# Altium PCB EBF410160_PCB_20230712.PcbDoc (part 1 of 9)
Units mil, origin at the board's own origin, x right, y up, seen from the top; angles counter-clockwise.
Board outline 5393.69 x 3858.26 mil, 6 copper layers (TOP, GND02, ART03, POW04, GND05, BOTTOM), stack 47.2 mil thick; 572 components, 434 nets, 2057 pads, 1177 vias.
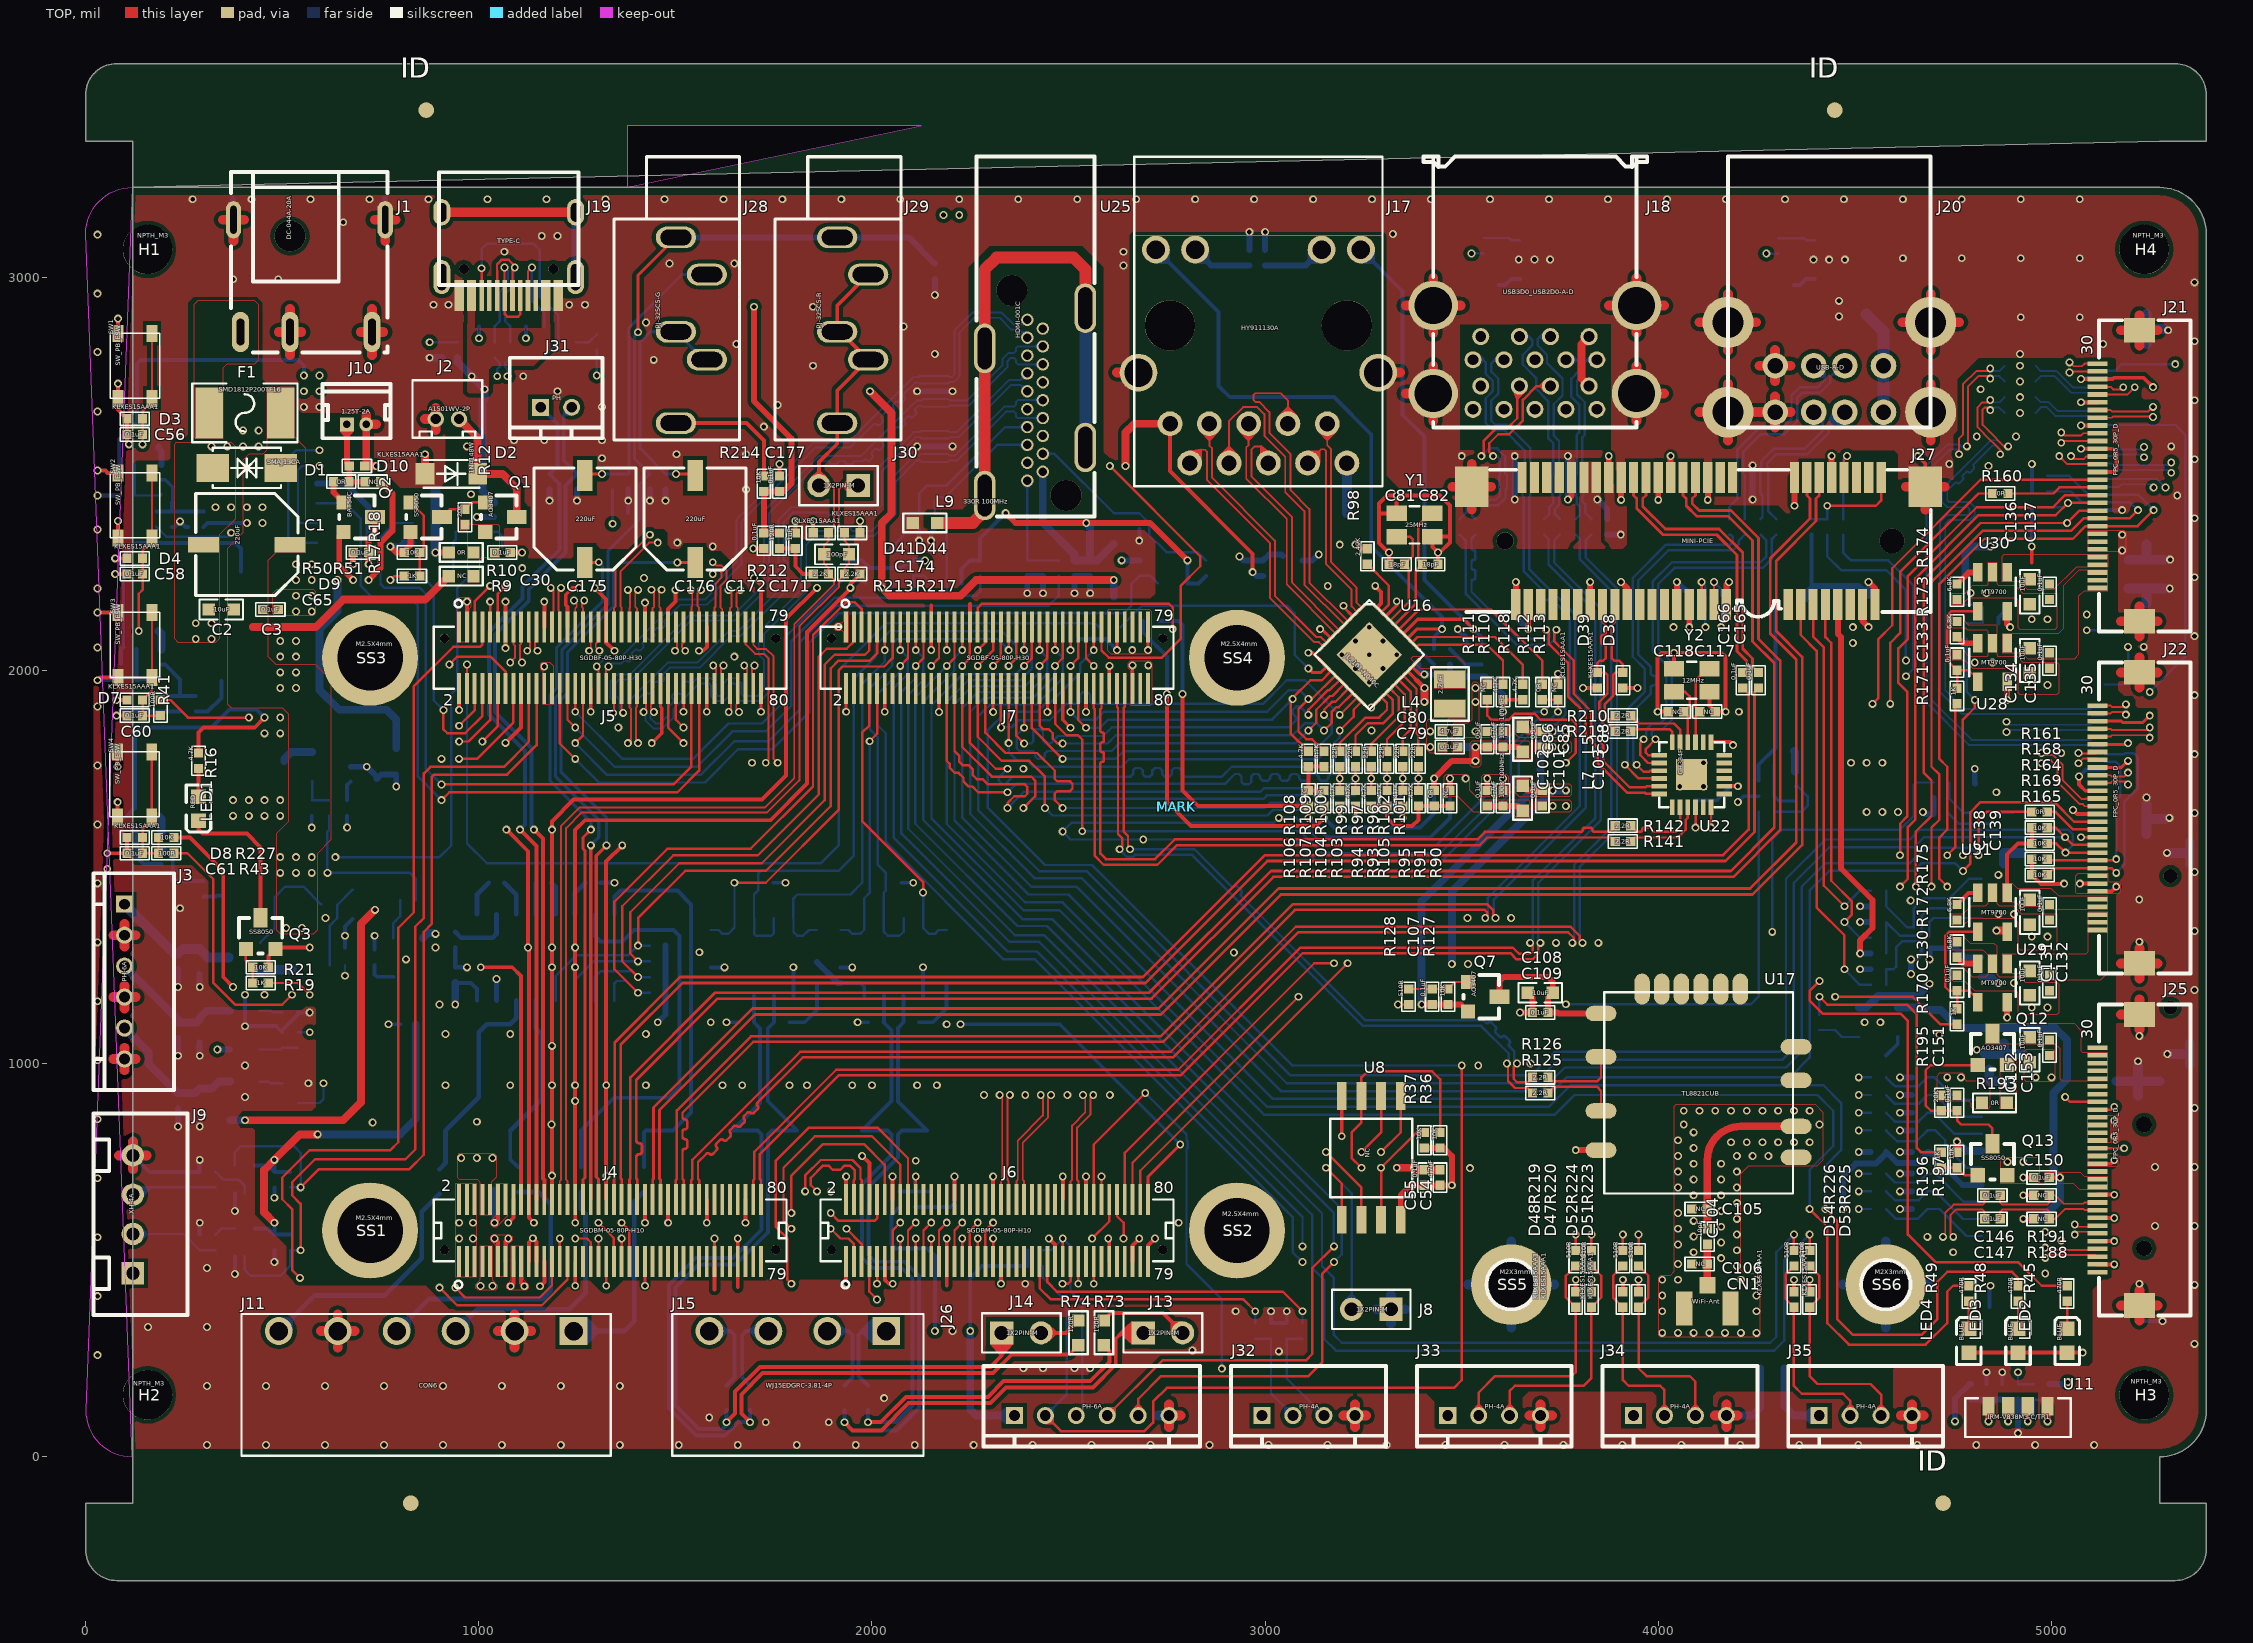
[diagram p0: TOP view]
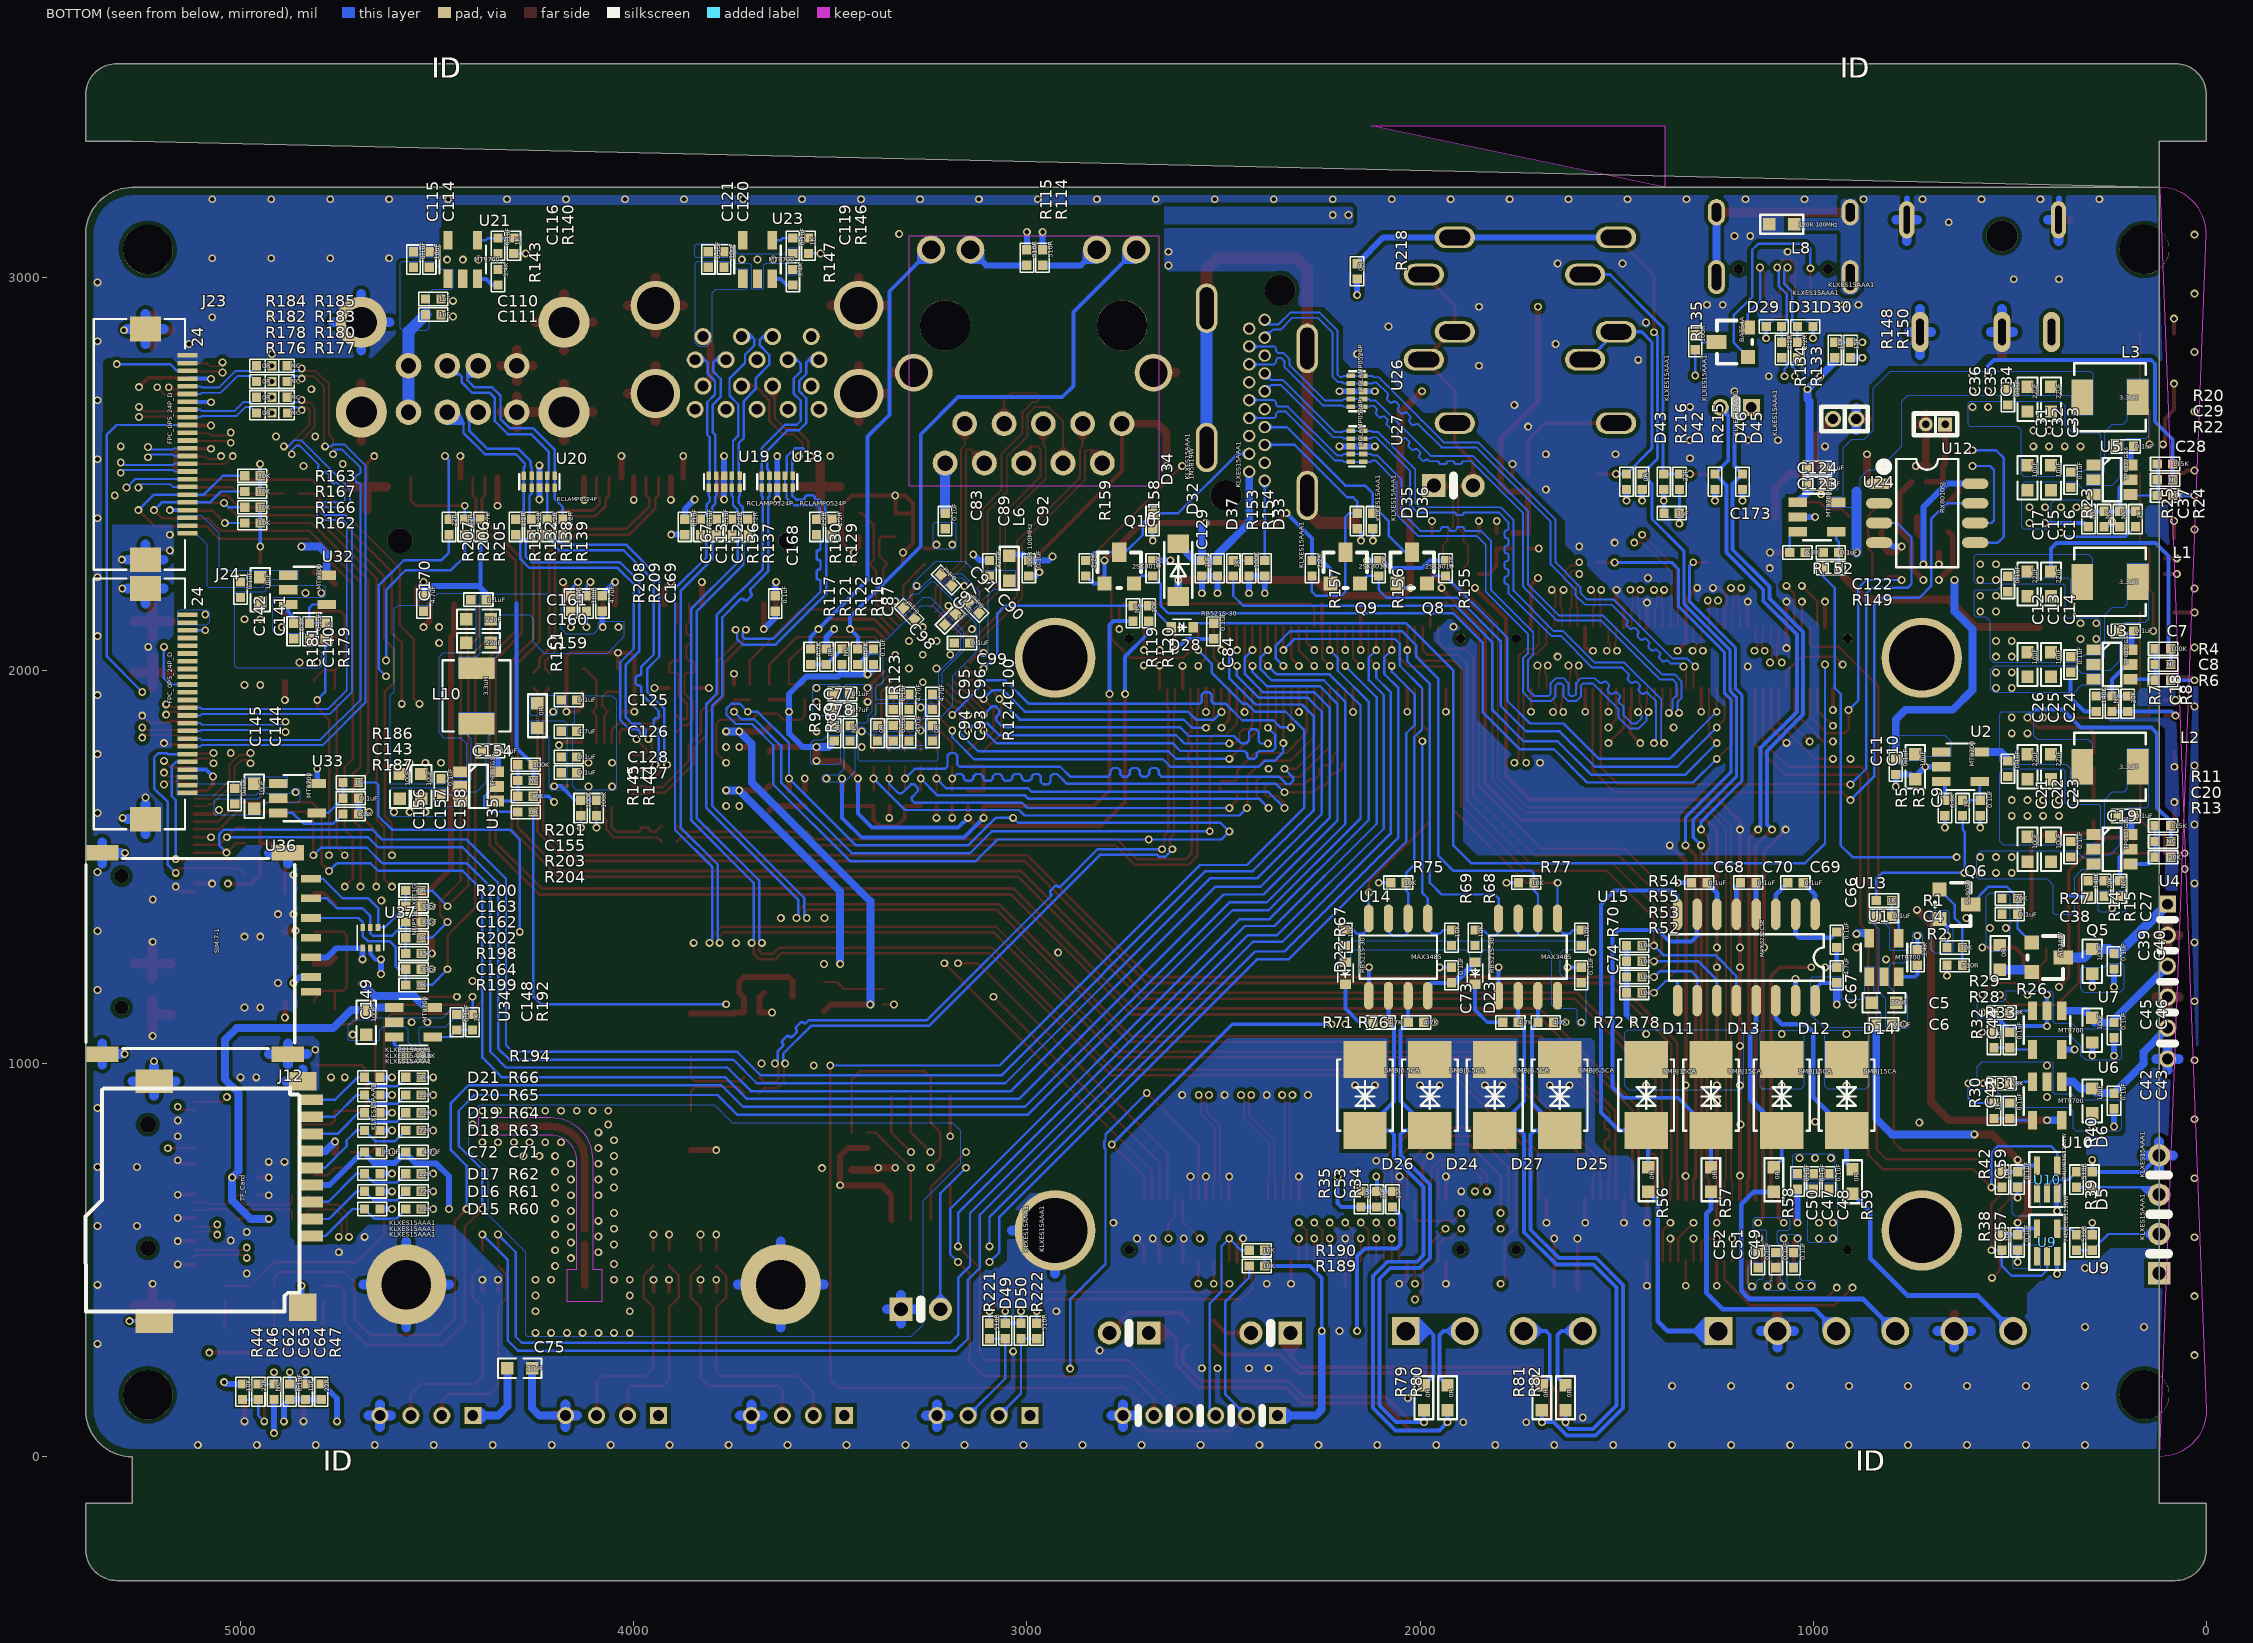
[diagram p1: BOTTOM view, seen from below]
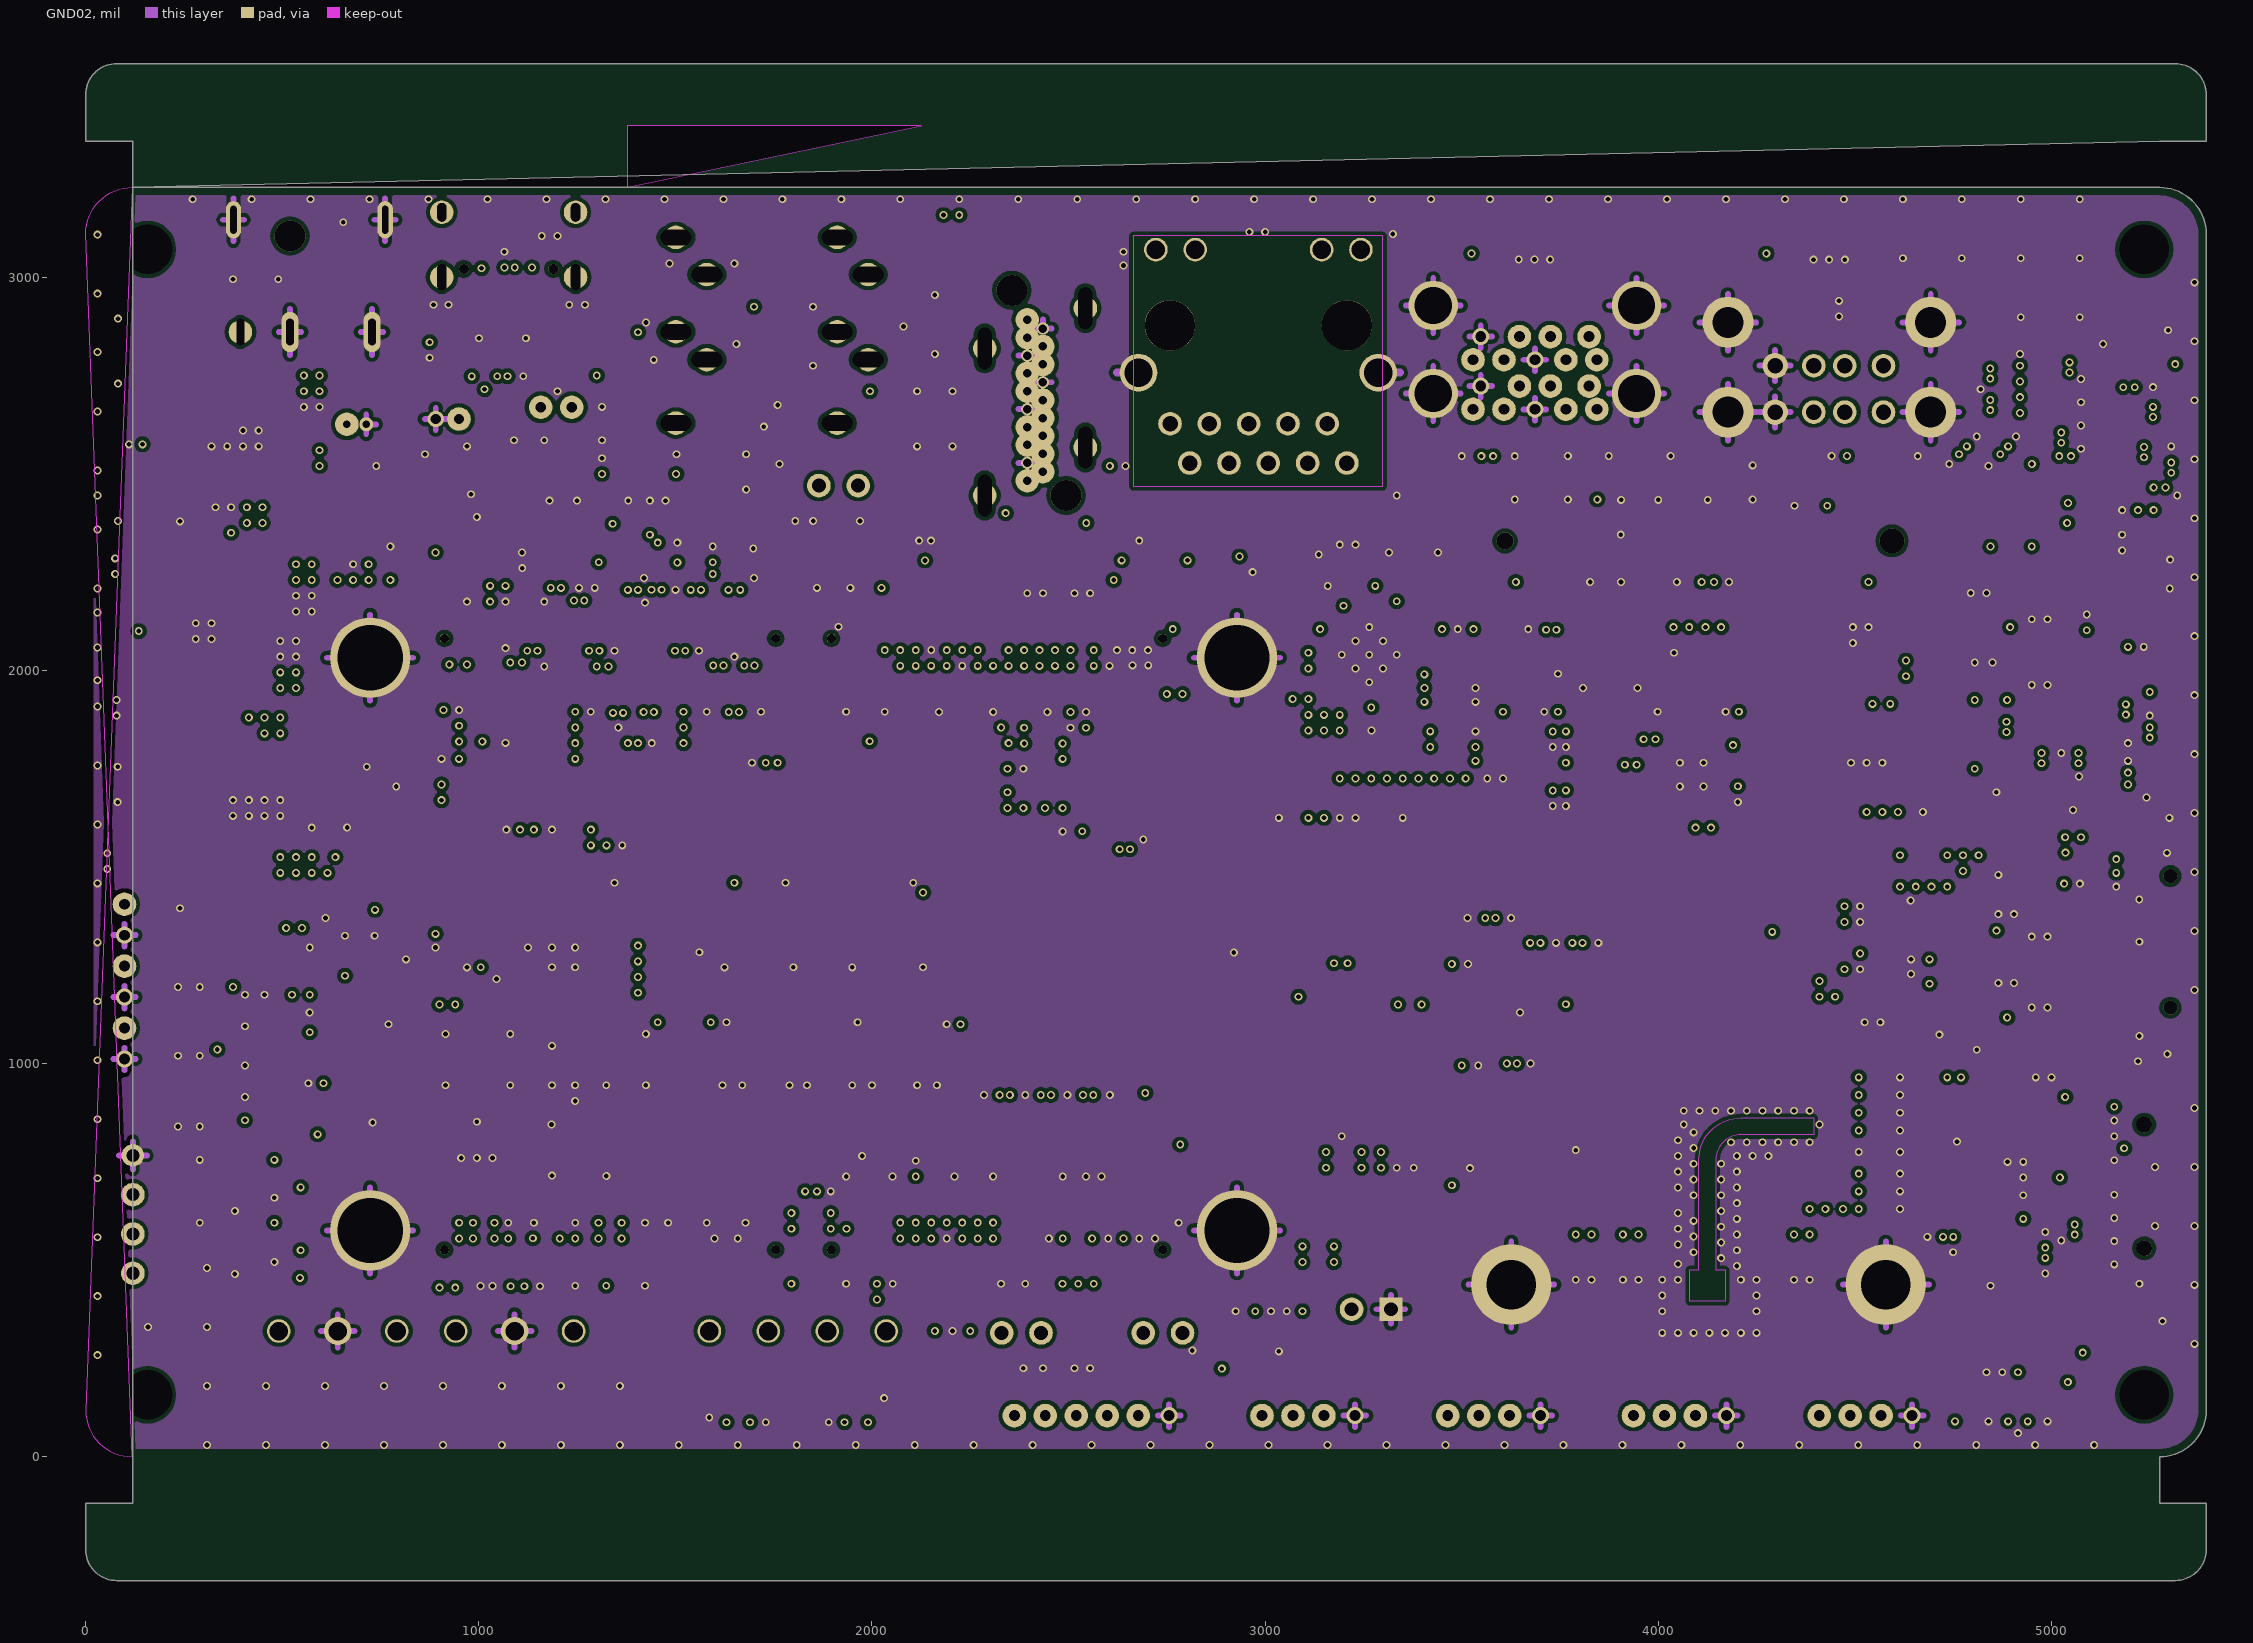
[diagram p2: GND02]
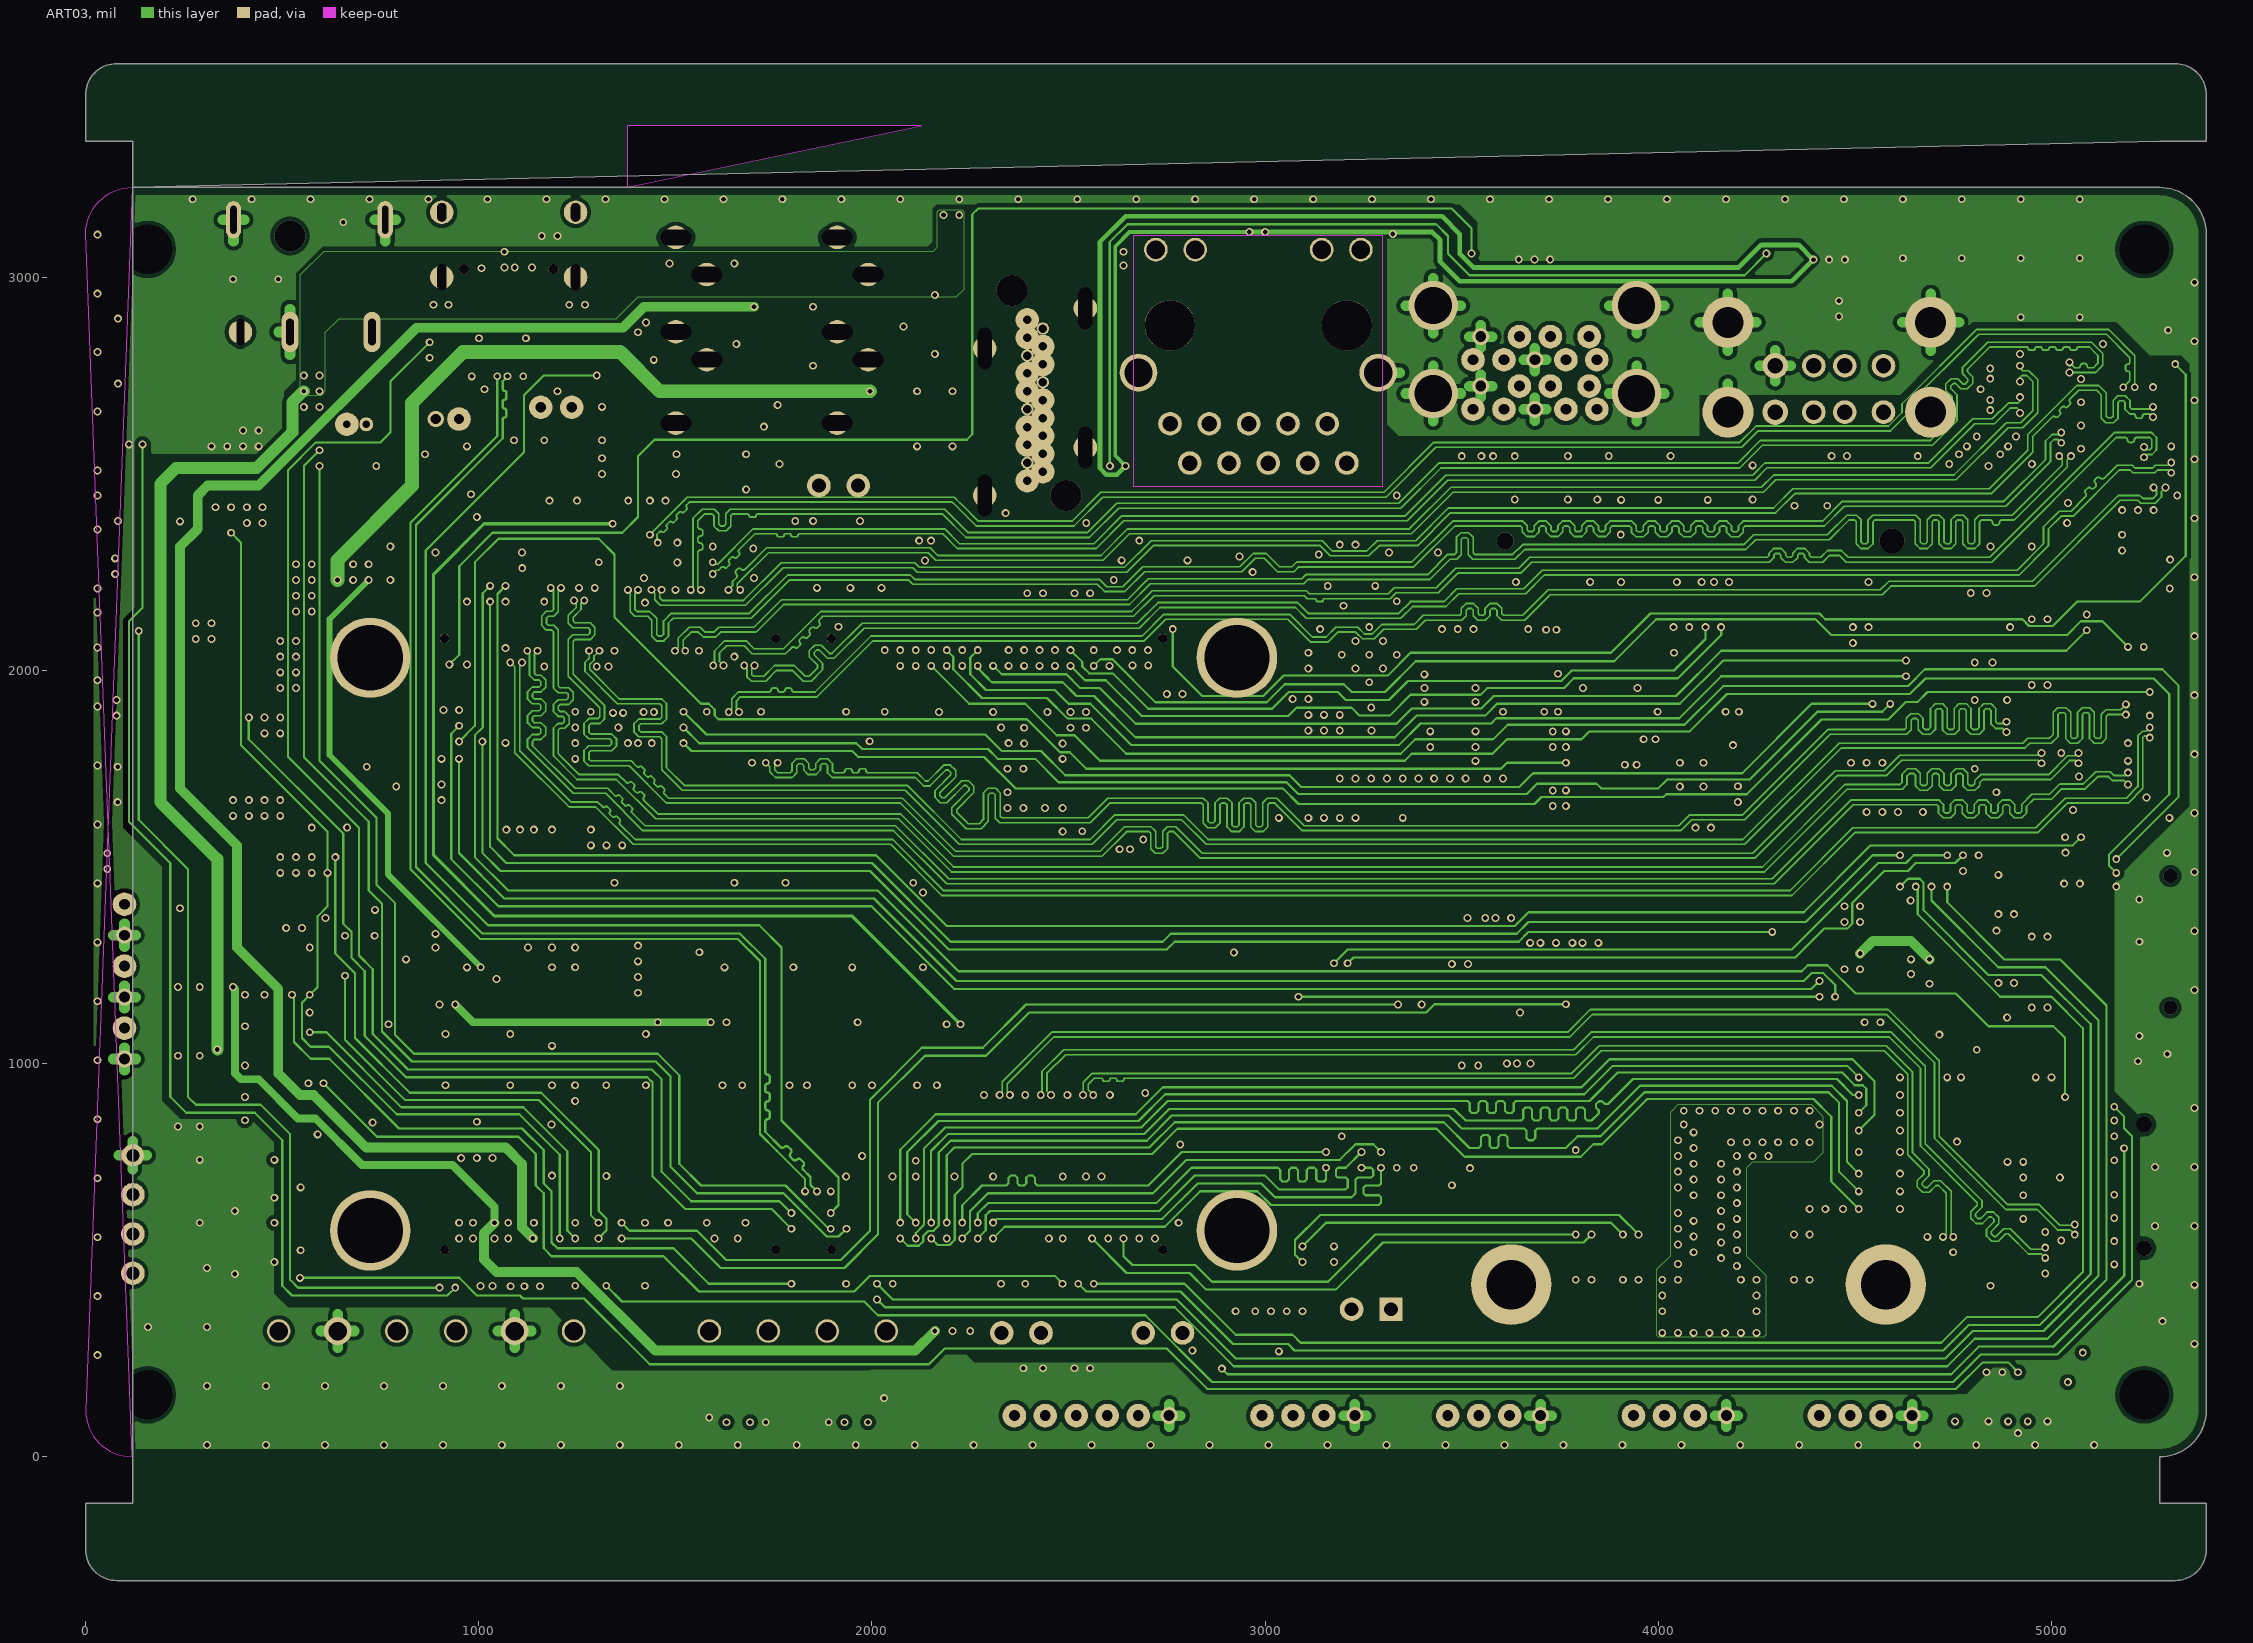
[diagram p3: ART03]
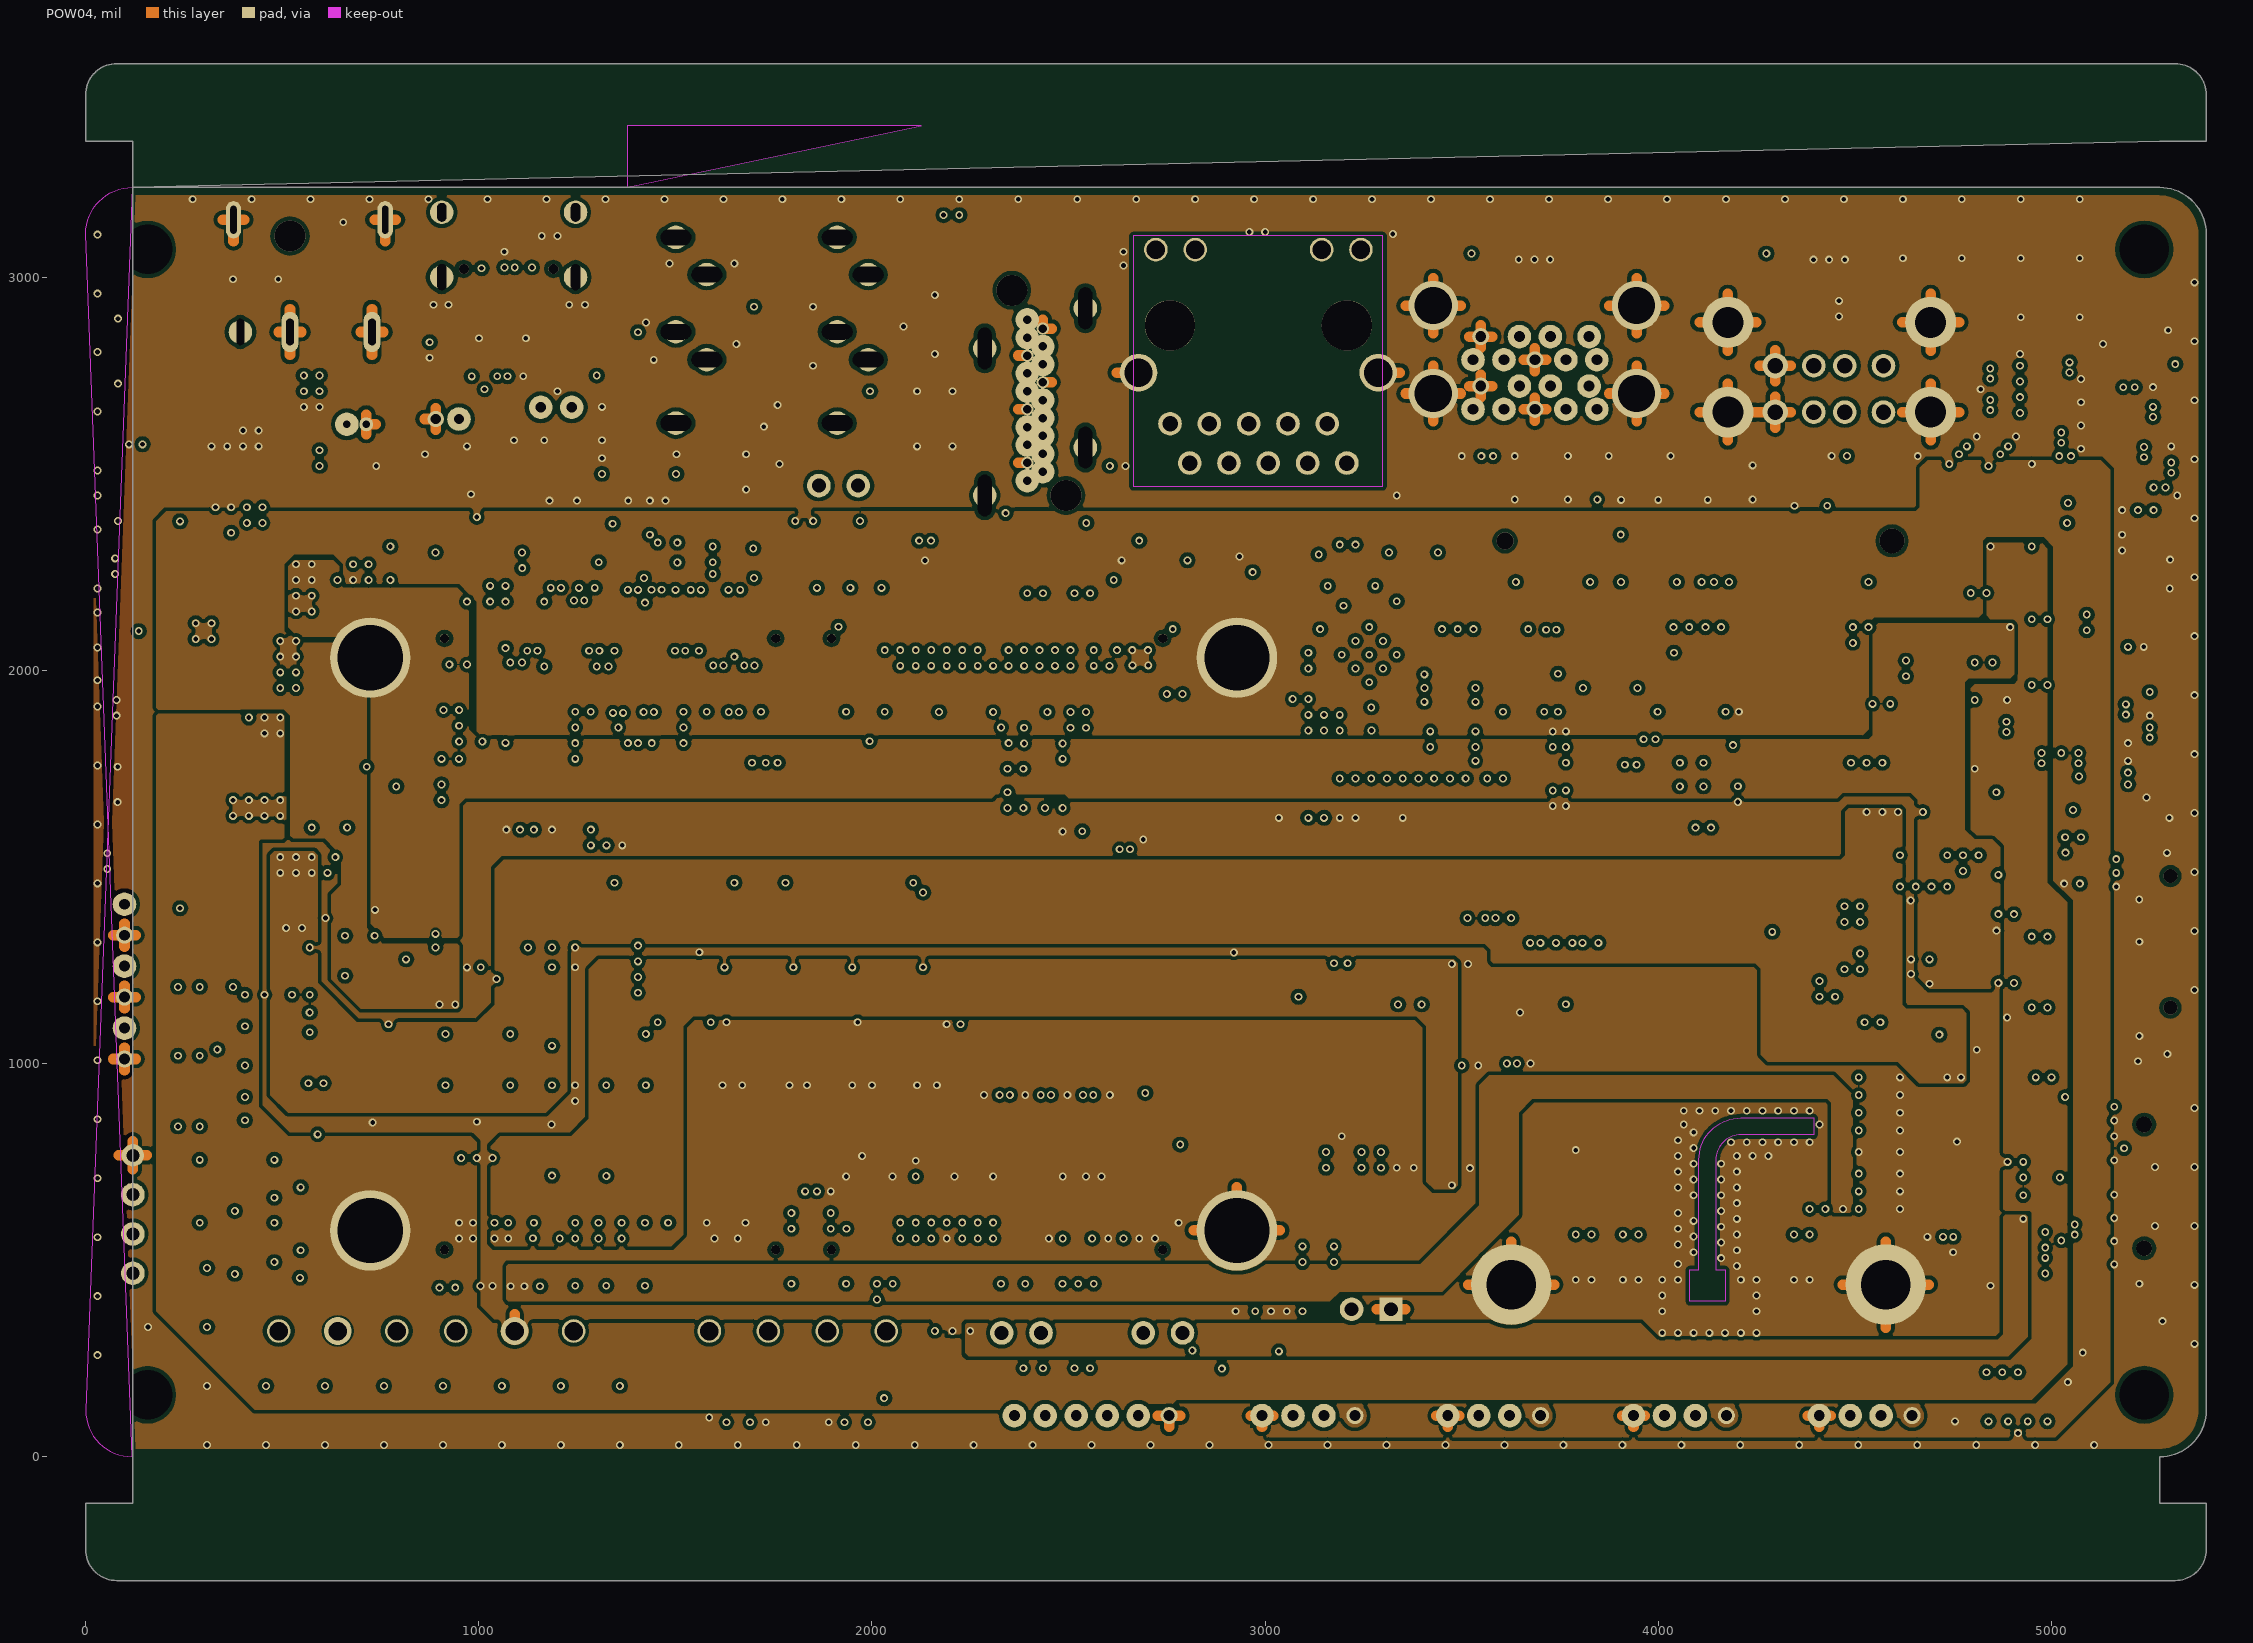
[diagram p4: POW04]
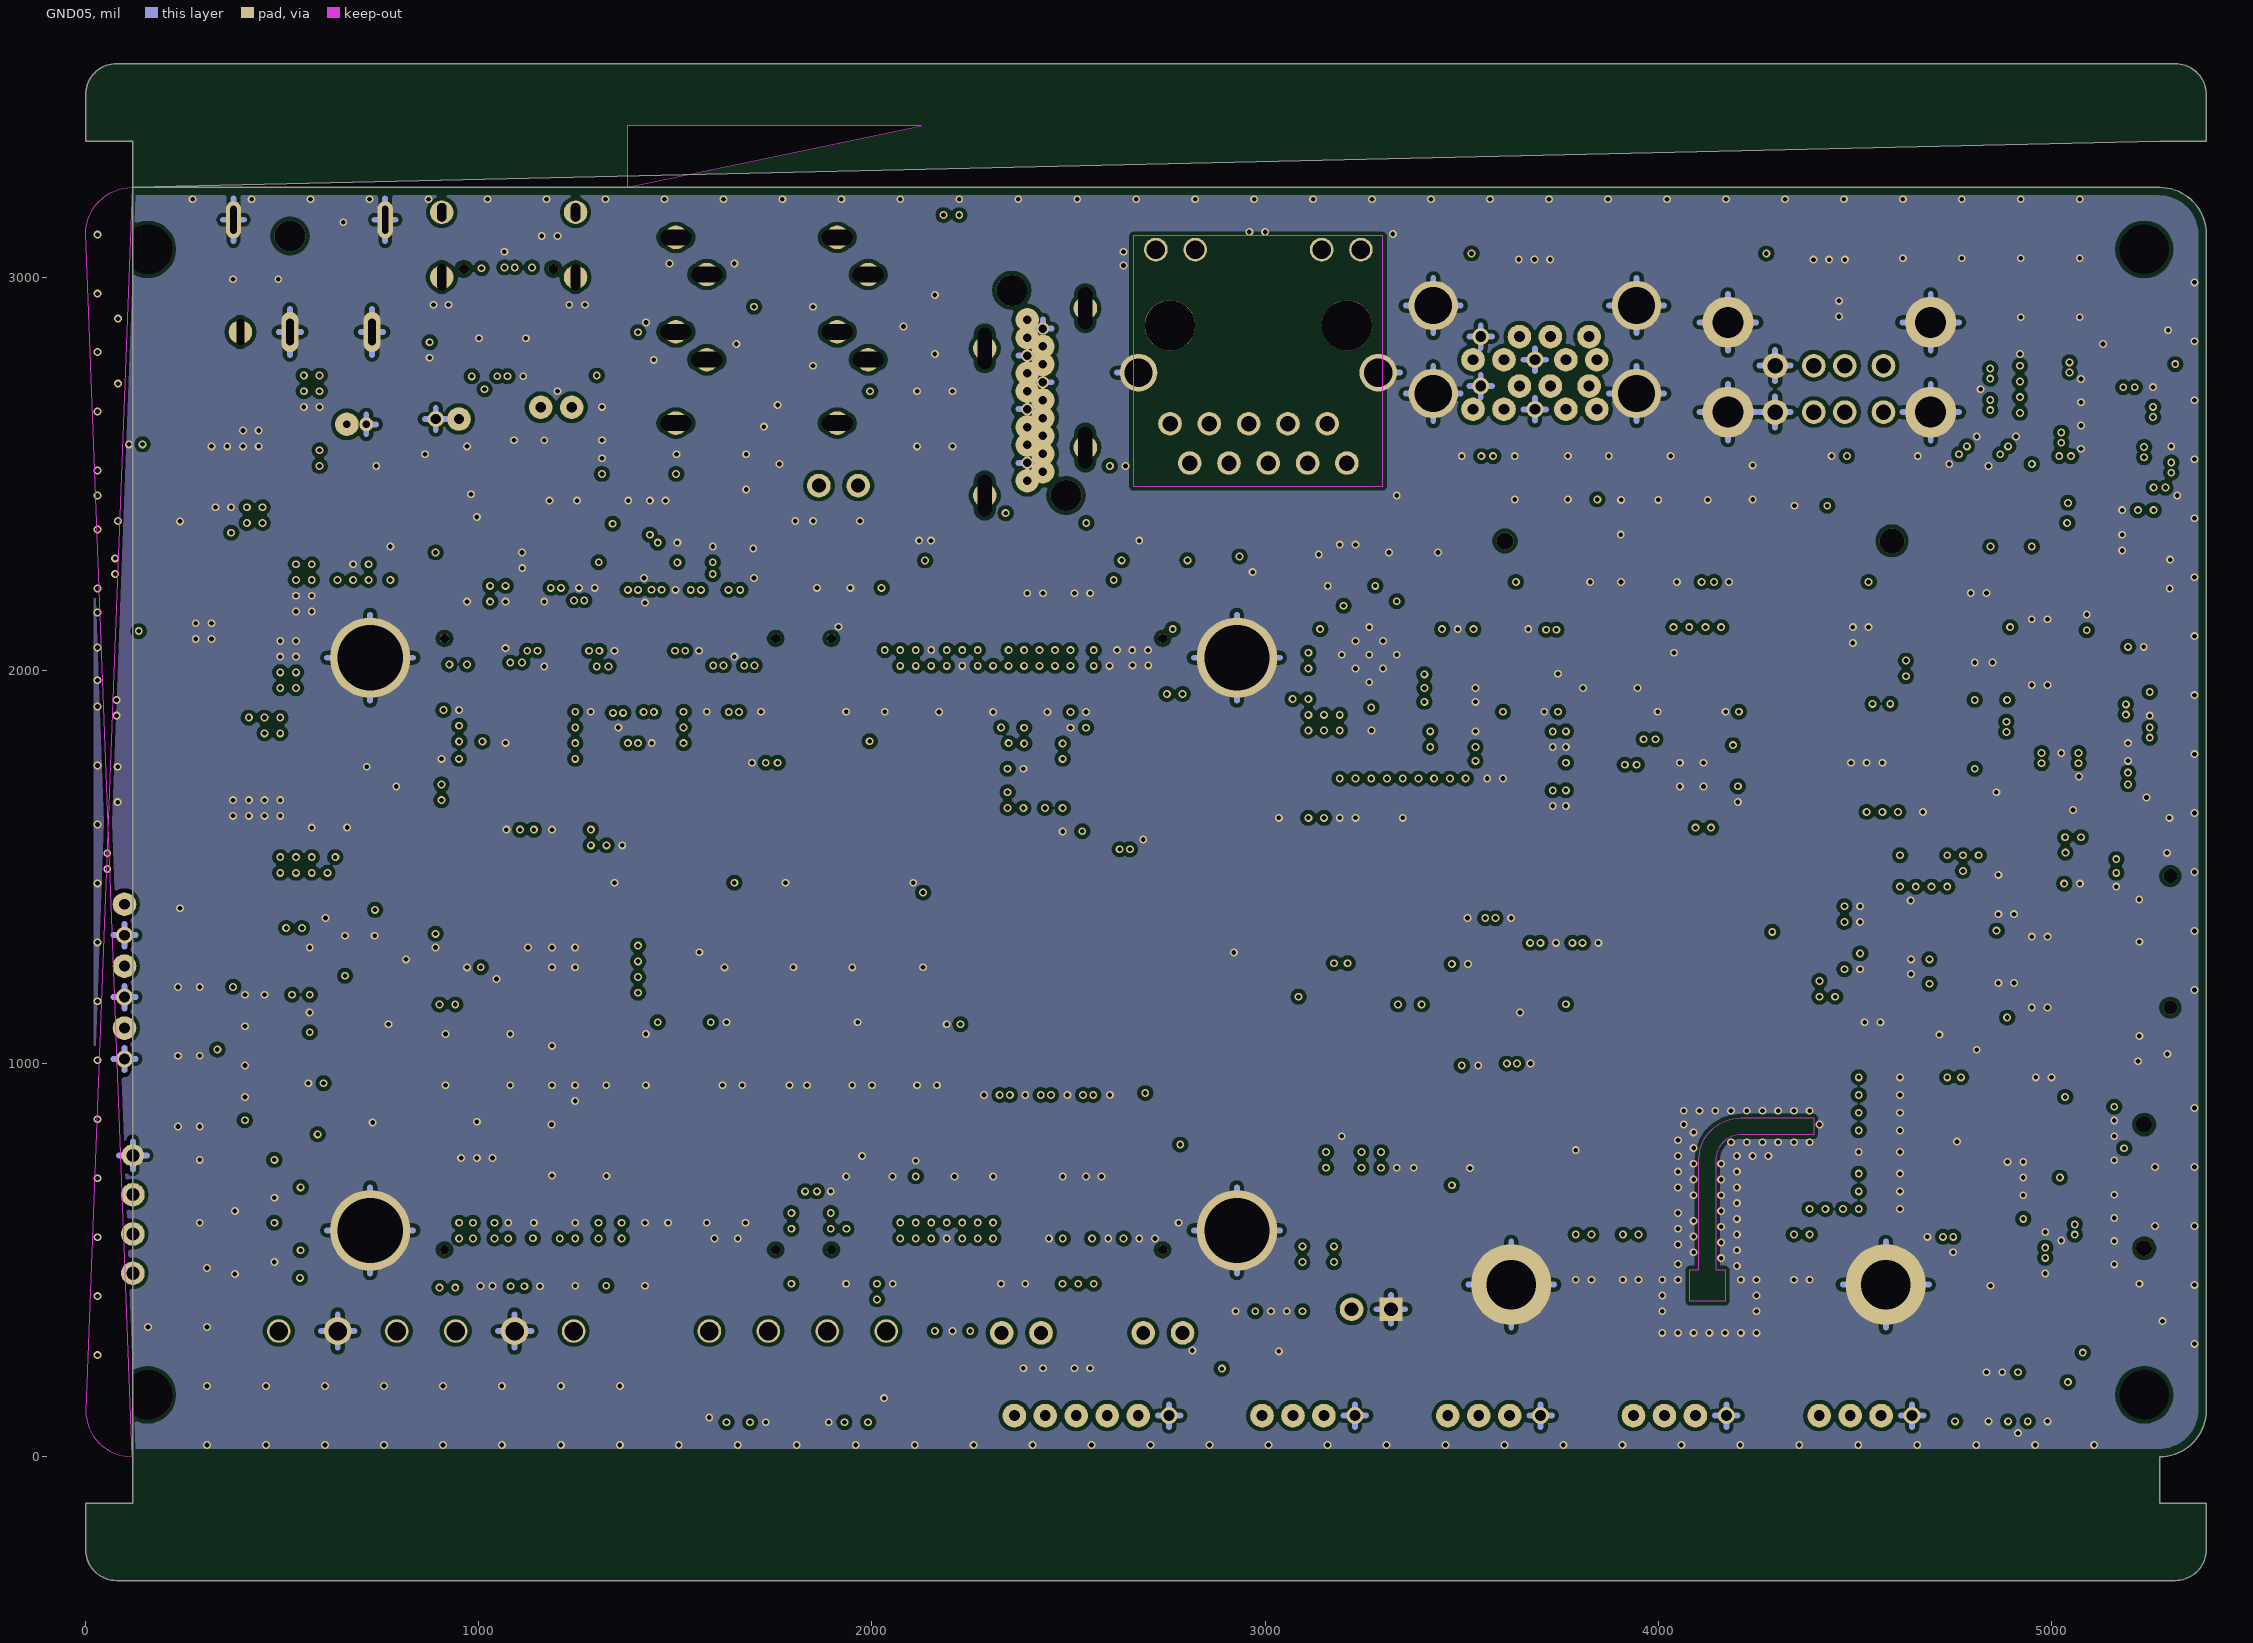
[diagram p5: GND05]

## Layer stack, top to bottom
Top Solder: solder mask 0.4, Solder Resist, Dk 3.5
TOP: signal copper 1.2
Dielectric 1: core 8, FR-4, Dk 4.5
GND02: signal copper 1.2
Dielectric2: core 8, FR-4, Dk 4.5
ART03: signal copper 1.2
Dielectric3: core 8, FR-4, Dk 4.5
POW04: signal copper 1.2
Dielectric4: core 8, FR-4, Dk 4.5
GND05: signal copper 1.2
Dielectric5: core 8, FR-4, Dk 4.5
BOTTOM: signal copper 1.2
Bottom Solder: solder mask 0.4, Solder Resist, Dk 3.5

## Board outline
120,3228.34 120,3346.45 0,3346.45 0,3464.56 cw(c78.74,3464.56) 78.74,3543.3 5314.95,3543.3 cw(c5314.95,3464.56) 5393.69,3464.56 5393.69,3346.45 5275.58,3346.45 118.11,3228.34 5275.58,3228.34 cw(c5275.58,3110.23) 5393.69,3110.23 5393.69,118.11 cw(c5275.58,118.11) 5275.58,0 5275.58,-118.11 5393.69,-118.11 5393.69,-236.22 cw(c5314.95,-236.22) 78.74,-314.96 cw(c78.74,-236.22) 0,-118.11 120,-118.11 120,0
cut-out: 0,3110.23 cw(c118.11,3110.23) 0,118.11 ccw(c118.11,118.11)
cut-out: 2125.98,3385.82 1377.95,3385.82 1377.95,3228.34

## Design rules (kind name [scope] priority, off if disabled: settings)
Clearance [All] p1: gap=10 ignorepadtopadclearanceinfootprint=FALSE except(0: Arc-Hole Track-Hole SMDPad-Hole THPad-Hole Via-Hole Fill-Hole Poly-Hole Region-Hole Text-Hole)
DiffPairsRouting [All] p1: maxlimit=10 minlimit=10 mostfreqgap=10 toplayer_minwidth=15 toplayer_maxwidth=15 toplayer_prefwidth=15 midlayer1_minwidth=15 midlayer1_maxwidth=15 midlayer1_prefwidth=15 midlayer2_minwidth=15 midlayer2_maxwidth=15 midlayer2_prefwidth=15 midlayer3_minwidth=15 midlayer3_maxwidth=15 midlayer3_prefwidth=15 midlayer4_minwidth=15 midlayer4_maxwidth=15 midlayer4_prefwidth=15 bottomlayer_minwidth=15 bottomlayer_maxwidth=15 bottomlayer_prefwidth=15 maxuncoupledlength=500
PlaneConnect [All] p1: planeconnectstyle=Direct reliefexpansion=20 reliefentries=4 reliefconductorwidth=10 reliefairgap=10
PolygonConnect [All] p1: connectstyle=Direct reliefconductorwidth=10 reliefentries=4 polygonreliefangle="90 Angle" airgapwidth=10
RoomDefinition RoomsKeepin1 [All vs False] p1: confinementstyle=ConfineIn formatcopy=TRUE lockcomponents=FALSE outline 40,3108.34 40.3,3115.31 41.22,3122.23 42.73,3129.05 44.82,3135.7 47.5,3142.15 50.72,3148.34 54.47,3154.23 58.72,3159.76 63.43,3164.91 68.58,3169.62 74.11,3173.87 80,3177.62 86.19,3180.84 92.64,3183.52 99.29,3185.61 106.11,3187.12 113.03,3188.04 120,3188.34 5273.69,3188.34 5280.66,3188.04 5287.58,3187.12 5294.4,3185.61 5301.05,3183.52 5307.5,3180.84 5313.69,3177.62 5319.58,3173.87 5325.11,3169.62 5330.26,3164.91 5334.97,3159.76 5339.22,3154.23 5342.97,3148.34 5346.19,3142.15 5348.87,3135.7 5350.96,3129.05 5352.47,3122.23 5353.39,3115.31 5353.69,3108.34 5353.69,120 5353.39,113.03 5352.47,106.11 5350.96,99.29 5348.87,92.64 5346.19,86.19 5342.97,80 5339.22,74.11 5334.97,68.58 5330.26,63.43 5325.11,58.72 5319.58,54.47 5313.69,50.72 5307.5,47.5 5301.05,44.82 5294.4,42.73 5287.58,41.22 5280.66,40.3 5273.69,40 120,40 113.03,40.3 106.11,41.22 99.29,42.73 92.64,44.82 86.19,47.5 80,50.72 74.11,54.47 68.58,58.72 63.43,63.43 58.72,68.58 54.47,74.11 50.72,80 47.5,86.19 44.82,92.64 42.73,99.29 41.22,106.11 40.3,113.03 40,120 40,3108.34
RoomDefinition RoomsKeepin0 [All vs False] p2: confinementstyle=ConfineIn formatcopy=TRUE lockcomponents=FALSE outline 40,3108.34 40.3,3115.31 41.22,3122.23 42.73,3129.05 44.82,3135.7 47.5,3142.15 50.72,3148.34 54.47,3154.23 58.72,3159.76 63.43,3164.91 68.58,3169.62 74.11,3173.87 80,3177.62 86.19,3180.84 92.64,3183.52 99.29,3185.61 106.11,3187.12 113.03,3188.04 120,3188.34 5273.69,3188.34 5280.66,3188.04 5287.58,3187.12 5294.4,3185.61 5301.05,3183.52 5307.5,3180.84 5313.69,3177.62 5319.58,3173.87 5325.11,3169.62 5330.26,3164.91 5334.97,3159.76 5339.22,3154.23 5342.97,3148.34 5346.19,3142.15 5348.87,3135.7 5350.96,3129.05 5352.47,3122.23 5353.39,3115.31 5353.69,3108.34 5353.69,120 5353.39,113.03 5352.47,106.11 5350.96,99.29 5348.87,92.64 5346.19,86.19 5342.97,80 5339.22,74.11 5334.97,68.58 5330.26,63.43 5325.11,58.72 5319.58,54.47 5313.69,50.72 5307.5,47.5 5301.05,44.82 5294.4,42.73 5287.58,41.22 5280.66,40.3 5273.69,40 120,40 113.03,40.3 106.11,41.22 99.29,42.73 92.64,44.82 86.19,47.5 80,50.72 74.11,54.47 68.58,58.72 63.43,63.43 58.72,68.58 54.47,74.11 50.72,80 47.5,86.19 44.82,92.64 42.73,99.29 41.22,106.11 40.3,113.03 40,120 40,3108.34
RoutingVias [All] p1: holewidth=28 width=50 viastyle="Through Hole" minholewidth=28 minwidth=50 maxholewidth=28 maxwidth=50
SolderMaskExpansion [All] p1: expansion=4 istentingtop=FALSE
Width [All] p1: maxlimit=10 minlimit=10 preferedwidth=10 impedanceprofiledriven=TRUE minimp=75.390000 maximp=75.390000 favimp=75.390000
28 further rules are at their usual default settings.

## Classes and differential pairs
net class ANTENNA: N18056634 N18056637
net class ANALOG: HP_DET HP_SNS HPL_OUT HPR_OUT N15830872 N15830941 N15838979 N15851038 SPKN_OUT SPKP_OUT
net class PWR_G: GND
differential pair DIFF_USB3_HOST1_SSTX: +USB3_HOST1_SSTXN -USB3_HOST1_SSTXP
differential pair DIFF_USB3_HOST1_SSRX: +USB3_HOST1_SSRXN -USB3_HOST1_SSRXP
differential pair DIFF_HOST1_D: +USB3_HOST1_DM -USB3_HOST1_DP
differential pair DIFF_USB2_HOST3_D: +USB2_HOST3_DM -USB2_HOST3_DP
differential pair DIFF_USB2_HOST2_D: +USB2_HOST2_DM -USB2_HOST2_DP
differential pair DIFF_OTG0_D: +USB_OTG0_DM -USB_OTG0_DP
differential pair DIFF_USB3_HOST1_SSTX: +SS_TXP -USB3_HOST1_SSTXN
differential pair DIFF_USB3_HOST1_SSTX: +SS_TXN -SS_TXP
differential pair DIFF_PCIE20_TX: +PE_TXN -PE_TXP
differential pair DIFF_PCIE20_TX: +PCIE20_TXP -PE_TXN
differential pair DIFF_PCIE20_TX: +PCIE20_TXN -PCIE20_TXP
differential pair DIFF_PCIE20_RXP: +PCIE20_RXN -PCIE20_RXP
differential pair DIFF_PCIE20_REFCLKP: +PCIE20_REFCLKN -PCIE20_REFCLKP
differential pair DIFF_OTG0_D: +OTG0_DP -USB_OTG0_DM
differential pair DIFF_OTG0_D: +OTG0_DM -OTG0_DP
differential pair DIFF_USB2_HOST2_D: +N18057335 -USB2_HOST2_DM
differential pair DIFF_USB2_HOST2_D: +N18057325 -N18057335
differential pair DIFF_USB2_HOST3_D: +N17770942 -USB2_HOST3_DM
differential pair DIFF_USB2_HOST3_D: +N17770939 -N17770942
differential pair DIFF_MIPI_DSI_TX1_D3P: +MIPI_DSI_TX1_D3N -MIPI_DSI_TX1_D3P
differential pair DIFF_MIPI_DSI_TX1_D2P: +MIPI_DSI_TX1_D2N -MIPI_DSI_TX1_D2P
differential pair DIFF_MIPI_DSI_TX1_D1P: +MIPI_DSI_TX1_D1N -MIPI_DSI_TX1_D1P
differential pair DIFF_MIPI_DSI_TX1_D0P: +MIPI_DSI_TX1_D0N -MIPI_DSI_TX1_D0P
differential pair DIFF_MIPI_DSI_TX1_CLKP: +MIPI_DSI_TX1_CLKN -MIPI_DSI_TX1_CLKP
differential pair DIFF_MIPI_DSI_TX0_D3P: +MIPI_DSI_TX0_D3N -MIPI_DSI_TX0_D3P
differential pair DIFF_MIPI_DSI_TX0_D2P: +MIPI_DSI_TX0_D2N -MIPI_DSI_TX0_D2P
differential pair DIFF_MIPI_DSI_TX0_D1P: +MIPI_DSI_TX0_D1N -MIPI_DSI_TX0_D1P
differential pair DIFF_MIPI_DSI_TX0_D0P: +MIPI_DSI_TX0_D0N -MIPI_DSI_TX0_D0P
differential pair DIFF_MIPI_DSI_TX0_CLKP: +MIPI_DSI_TX0_CLKN -MIPI_DSI_TX0_CLKP
differential pair DIFF_CSI_RX_D3: +MIPI_CSI_RX_D3N -MIPI_CSI_RX_D3P
differential pair DIFF_MIPI_CSI_RX_D2: +MIPI_CSI_RX_D2N -MIPI_CSI_RX_D2P
differential pair DIFF_MIPI_CSI_RX_D1P: +MIPI_CSI_RX_D1N -MIPI_CSI_RX_D1P
differential pair DIFF_MIPI_CSI_RX_D0P: +MIPI_CSI_RX_D0N -MIPI_CSI_RX_D0P
differential pair DIFF_MIPI_CSI_RX_CLK1P: +MIPI_CSI_RX_CLK1N -MIPI_CSI_RX_CLK1P
differential pair DIFF_MIPI_CSI_RX_CLK0P: +MIPI_CSI_RX_CLK0N -MIPI_CSI_RX_CLK0P
differential pair DIFF_MIC: +MIC_INN -MIC_INP
differential pair DIFF_MDI3_PHY: +MDIN3_PHY -MDIP3_PHY
differential pair DIFF_MDI2_PHY: +MDIN2_PHY -MDIP2_PHY
differential pair DIFF_MDI1_PHY: +MDIN1_PHY -MDIP1_PHY
differential pair DIFF_MDI0_PHY: +MDIN0_PHY -MDIP0_PHY
differential pair DIFF_HUB_D4: +HUB_DM4 -HUB_DP4
differential pair DIFF_HUB_D3: +HUB_DM3 -HUB_DP3
differential pair DIFF_HUB_D2: +HUB_DM2 -HUB_DP2
differential pair DIFF_HUB_D1: +HUB_DM1 -HUB_DP1
differential pair DIFF_HOST1_D: +HOST1_DP -USB3_HOST1_DM
differential pair DIFF_HOST1_D: +HOST1_DM -HOST1_DP
differential pair DIFF_HDMI_TXCLK_PORT: +HDMI_TXCLKN_PORT -HDMI_TXCLKP_PORT
differential pair DIFF_HDMI_TX2_PORT: +HDMI_TX2N_PORT -HDMI_TX2P_PORT
differential pair DIFF_HDMI_TX1_PORT: +HDMI_TX1N_PORT -HDMI_TX1P_PORT
differential pair DIFF_HDMI_TX0_PORT: +HDMI_TX0N_PORT -HDMI_TX0P_PORT
differential pair DIFF_ED_TX_D1P: +EDP_TX_D1N -EDP_TX_D1P
differential pair DIFF_ED_TX_D0P: +EDP_TX_D0N -EDP_TX_D0P
differential pair DIFF_ED_AUXP: +EDP_TX_AUXN -EDP_TX_AUXP
differential pair DIFF_ED_AUXP: +EDP_AUXP -EDP_TX_AUXN
differential pair DIFF_ED_AUXP: +EDP_AUXN -EDP_AUXP
differential pair DIFF_HUB_D4: +DP4 -HUB_DM4
differential pair DIFF_HUB_D4: +DM4 -DP4
differential pair DIFF_CSI_RX_D3: +CSI_RX_D3P_S1 -MIPI_CSI_RX_D3N
differential pair DIFF_CSI_RX_D3: +CSI_RX_D3P_S0 -CSI_RX_D3P_S1
differential pair DIFF_CSI_RX_D3: +CSI_RX_D3N_S1 -CSI_RX_D3P_S0
differential pair DIFF_CSI_RX_D3: +CSI_RX_D3N_S0 -CSI_RX_D3N_S1
differential pair DIFF_MIPI_CSI_RX_D2: +CSI_RX_D2P_S1 -MIPI_CSI_RX_D2N
differential pair DIFF_MIPI_CSI_RX_D2: +CSI_RX_D2P_S0 -CSI_RX_D2P_S1
differential pair DIFF_MIPI_CSI_RX_D2: +CSI_RX_D2N_S1 -CSI_RX_D2P_S0
differential pair DIFF_MIPI_CSI_RX_D2: +CSI_RX_D2N_S0 -CSI_RX_D2N_S1
differential pair DIFF_HUB_D3: +B_DP3 -HUB_DM3
differential pair DIFF_HUB_D2: +B_DP2 -HUB_DM2
differential pair DIFF_HUB_D1: +B_DP1 -HUB_DM1
differential pair DIFF_HUB_D3: +B_DM3 -B_DP3
differential pair DIFF_HUB_D2: +B_DM2 -B_DP2
differential pair DIFF_HUB_D1: +B_DM1 -B_DP1

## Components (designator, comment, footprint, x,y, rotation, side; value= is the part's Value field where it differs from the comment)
C1 "CAP_EC6P3_220UF" EC6P3 410,2320 r270 top
C2 "CAP_NP_C0603_DISCRETE_10UF" C0603#1 345,2155 r180 top
C3 "CAP_NP_C0402_DISCRETE_0.1UF" C0402#1 470,2155 r0 top
C4 "CAP_NP_C0402_DISCRETE_0.1UF" C0402#1 820,1375 r0 bottom
C5 "CAP_NP_C0603_DISCRETE_10UF" C0603#2 820,1155 r0 bottom
C6 "CAP_NP_C0402_DISCRETE_0.1UF" C0402#2 820,1100 r0 bottom
C7 "CAP_NP_C0402_DISCRETE_0.1UF" C0402#1 205,2100 r0 bottom
C8 "CAP_NP_C0402_DISCRETE_NC" C0402#1 110,2015 r0 bottom
C9 "CAP_NP_C0402_DISCRETE_0.1UF" C0402#1 575,1650 r270 bottom
C10 "CAP_NP_C0603_DISCRETE_10UF" C0603#1 740,1755 r270 bottom
C11 "CAP_NP_C0402_DISCRETE_0.1UF" C0402#1 790,1755 r270 bottom
C12 "CAP_NP_C0603_DISCRETE_10UF" C0603#1 455,2015 r90 bottom
C13 "CAP_NP_C0603_DISCRETE_10UF" C0603#1 395,2015 r90 bottom
C14 "CAP_NP_C0402_DISCRETE_0.1UF" C0402#1 345,2015 r90 bottom
C15 "CAP_NP_C0603_DISCRETE_22UF" C0603#1 455,2220 r270 bottom
C16 "CAP_NP_C0603_DISCRETE_22UF" C0603#1 395,2220 r270 bottom
C17 "CAP_NP_C0402_DISCRETE_0.1UF" C0402#1 505,2220 r270 bottom
C18 "CAP_NP_C0402_DISCRETE_NC" C0402#1 240,1915 r90 bottom
C19 "CAP_NP_C0402_DISCRETE_0.1UF" C0402#1 205,1630 r0 bottom
C20 "CAP_NP_C0402_DISCRETE_NC" C0402#1 110,1565 r0 bottom
C21 "CAP_NP_C0603_DISCRETE_10UF" C0603#1 455,1545 r90 bottom
C22 "CAP_NP_C0603_DISCRETE_10UF" C0603#1 395,1545 r90 bottom
C23 "CAP_NP_C0402_DISCRETE_0.1UF" C0402#1 345,1545 r90 bottom
C24 "CAP_NP_C0603_DISCRETE_22UF" C0603#1 395,1755 r270 bottom
C25 "CAP_NP_C0603_DISCRETE_22UF" C0603#1 455,1755 r270 bottom
C26 "CAP_NP_C0402_DISCRETE_0.1UF" C0402#1 505,1750 r270 bottom
C27 "CAP_NP_C0402_DISCRETE_NC" C0402#1 220,1445 r90 bottom
C28 "CAP_NP_C0402_DISCRETE_0.1UF" C0402#1 205,2570 r0 bottom
C29 "CAP_NP_C0402_DISCRETE_NC" C0402#1 105,2485 r0 bottom
C30 "CAP_NP_C0402_DISCRETE_0.1UF" C0402#1 1060,2300 r0 top
C31 "CAP_NP_C0603_DISCRETE_10UF" C0603#1 455,2490 r90 bottom
C32 "CAP_NP_C0603_DISCRETE_10UF" C0603#1 395,2490 r90 bottom
C33 "CAP_NP_C0402_DISCRETE_0.1UF" C0402#1 345,2485 r90 bottom
C34 "CAP_NP_C0603_DISCRETE_22UF" C0603#1 395,2690 r270 bottom
C35 "CAP_NP_C0603_DISCRETE_22UF" C0603#1 455,2690 r270 bottom
C36 "CAP_NP_C0402_DISCRETE_0.1UF" C0402#1 505,2695 r270 bottom
C37 "CAP_NP_C0402_DISCRETE_NC" C0402#1 220,2385 r90 bottom
C38 "CAP_NP_C0402_DISCRETE_0.1UF" C0402#2 500,1380 r0 bottom
C39 "CAP_NP_C0603_DISCRETE_10UF" C0603#1 290,1260 r270 bottom
C40 "CAP_NP_C0402_DISCRETE_0.1UF" C0402#1 235,1260 r270 bottom
C41 "CAP_NP_C0402_DISCRETE_0.1UF" C0402#1 500,880 r90 bottom
C42 "CAP_NP_C0603_DISCRETE_10UF" C0603#1 290,905 r270 bottom
C43 "CAP_NP_C0402_DISCRETE_0.1UF" C0402#1 235,905 r270 bottom
C44 "CAP_NP_C0402_DISCRETE_0.1UF" C0402#1 500,1060 r90 bottom
C45 "CAP_NP_C0603_DISCRETE_10UF" C0603#1 290,1085 r270 bottom
C46 "CAP_NP_C0402_DISCRETE_0.1UF" C0402#1 235,1085 r270 bottom
C47 "CAP_NP_C0402_DISCRETE_0.1UF" C0402#1 1000,700 r90 bottom
C48 "CAP_NP_C0402_DISCRETE_0.1UF" C0402#1 960,700 r90 bottom
C49 "CAP_NP_C0402_DISCRETE_0.1UF" C0402#1 1050,500 r270 bottom
C50 "CAP_NP_C0402_DISCRETE_0.1UF" C0402#1 1040,700 r90 bottom
C51 "CAP_NP_C0402_DISCRETE_0.1UF" C0402#1 1095,500 r90 bottom
C52 "CAP_NP_C0402_DISCRETE_0.1UF" C0402#1 1140,500 r270 bottom
C53 "CAP_NP_C0402_DISCRETE_1UF" C0402#1 2110,655 r270 bottom
C54 "CAP_NP_C0402_DISCRETE_4.7UF" C0402#1 3445,710 r90 top
C55 "CAP_NP_C0402_DISCRETE_0.1UF" C0402#1 3405,710 r90 top
C56 "CAP_NP_C0402_DISCRETE_0.1UF" C0402#1 125,2600 r180 top
C57 "CAP_NP_C0402_DISCRETE_0.1UF" C0402#1 480,545 r270 bottom
C58 "CAP_NP_C0402_DISCRETE_0.1UF" C0402#1 125,2245 r180 top
C59 "CAP_NP_C0402_DISCRETE_0.1UF" C0402#1 480,705 r270 bottom
C60 "CAP_NP_C0402_DISCRETE_0.1UF" C0402#1 125,1885 r180 top
C61 "CAP_NP_C0402_DISCRETE_0.1UF" C0402#1 125,1535 r180 top
C62 "CAP_NP_C0402_DISCRETE_NC" C0402#1 4915,165 r270 bottom
C63 "CAP_NP_C0402_DISCRETE_0.1UF" C0402#1 4875,165 r90 bottom
C64 "CAP_NP_C0402_DISCRETE_1UF" C0402#1 4835,165 r90 bottom
C65 "CAP_NP_C0402_DISCRETE_0.1UF" C0402#1 700,2300 r180 top
C66 "CAP_NP_C0402_DISCRETE_0.1UF" C0402#1 940,1315 r270 bottom
C67 "CAP_NP_C0402_DISCRETE_4.7UF" C0402#1 940,1225 r90 bottom
C68 "CAP_NP_C0402_DISCRETE_0.1UF" C0402#1 1290,1460 r0 bottom
C69 "CAP_NP_C0402_DISCRETE_0.1UF" C0402#2 1045,1460 r0 bottom
C70 "CAP_NP_C0402_DISCRETE_0.1UF" C0402#2 1165,1460 r0 bottom
C71 "CAP_NP_C0402_DISCRETE_4.7UF" C0402#2 4560,775 r0 bottom
C72 "CAP_NP_C0402_DISCRETE_0.1UF" C0402#2 4665,775 r0 bottom
C73 "CAP_NP_C0402_DISCRETE_0.1UF" C0402#1 1920,1225 r90 bottom
C74 "CAP_NP_C0402_DISCRETE_0.1UF" C0402#1 1590,1225 r90 bottom
C75 "CAP_NP_C0603_DISCRETE_10UF" C0603#2 4290,225 r0 bottom
C77 "CAP_NP_C0402_DISCRETE_0.1UF" C0402#1 3470,1940 r0 bottom
C78 "CAP_NP_C0402_DISCRETE_4.7UF" C0402#1 3470,1900 r0 bottom
C79 "CAP_NP_C0402_DISCRETE_0.1UF" C0402#1 3470,1805 r0 top
C80 "CAP_NP_C0402_DISCRETE_4.7UF" C0402#1 3470,1845 r0 top
C81 "CAP_NP_C0402_DISCRETE_18PF" C0402#1 3335,2270 r180 top
C82 "CAP_NP_C0402_DISCRETE_18PF" C0402#1 3420,2270 r0 top
C83 "CAP_NP_C0402_DISCRETE_0.1UF" C0402#1 3208,2380 r270 bottom
C84 "CAP_NP_C0402_DISCRETE_0.1UF" C0402#1 2525,2100 r270 bottom
C85 "CAP_NP_C0402_DISCRETE_4.7UF" C0402#1 3605,1825 r90 top
C86 "CAP_NP_C0402_DISCRETE_0.1UF" C0402#1 3565,1825 r90 top
C87 "CAP_NP_C0402_DISCRETE_0.1UF" C0402#1 3390,2035 r90 bottom
C88 "CAP_NP_C0402_DISCRETE_0.1UF" C0402#1 3705,1825 r270 top
C89 "CAP_NP_C0402_DISCRETE_4.7UF" C0402#1 3095,2260 r90 bottom
C90 "CAP_NP_C0402_DISCRETE_0.1UF" C0402#1 3135,2160 r45 bottom
C91 "CAP_NP_C0402_DISCRETE_0.1UF" C0402#1 3205,2230 r225 bottom
C92 "CAP_NP_C0402_DISCRETE_0.1UF" C0402#1 2995,2260 r270 bottom
C93 "CAP_NP_C0402_DISCRETE_4.7UF" C0402#1 3300,1840 r270 bottom
C94 "CAP_NP_C0402_DISCRETE_0.1UF" C0402#1 3340,1840 r270 bottom
C95 "CAP_NP_C0402_DISCRETE_0.1UF" C0402#1 3340,1920 r90 bottom
C96 "CAP_NP_C0402_DISCRETE_4.7UF" C0402#1 3300,1920 r90 bottom
C97 "CAP_NP_C0402_DISCRETE_0.1UF" C0402#1 3195,2130 r315 bottom
C98 "CAP_NP_C0402_DISCRETE_0.1UF" C0402#1 3300,2145 r225 bottom
C99 "CAP_NP_C0402_DISCRETE_0.1UF" C0402#1 3165,2070 r0 bottom
C100 "CAP_NP_C0402_DISCRETE_4.7UF" C0402#1 3240,1920 r90 bottom
C101 "CAP_NP_C0402_DISCRETE_4.7UF" C0402#1 3605,1675 r90 top
C102 "CAP_NP_C0402_DISCRETE_0.1UF" C0402#1 3565,1675 r90 top
C103 "CAP_NP_C0402_DISCRETE_0.1UF" C0402#1 3705,1675 r270 top
C104 "CAP_NP_C0402_DISCRETE_10PF" C0402#1 4125,560 r270 top
C105 "CAP_NP_C0402_DISCRETE_NC" C0402#1 4105.1,630 r180 top
C106 "CAP_NP_C0402_DISCRETE_NC" C0402#1 4105,490 r180 top
C107 "CAP_NP_C0402_DISCRETE_0.1UF" C0402#1 3425,1170 r90 top
C108 "CAP_NP_C0603_DISCRETE_10UF" C0603#1 3700,1180 r180 top
C109 "CAP_NP_C0402_DISCRETE_0.1UF" C0402#1 3700,1130 r180 top
C110 "CAP_NP_C0402_DISCRETE_1UF" C0402#2 4510,2945 r0 bottom
C111 "CAP_NP_C0402_DISCRETE_1UF" C0402#2 4510,2905 r0 bottom
C112 "CAP_NP_C0402_DISCRETE_0.1UF" C0402#1 3790,2365 r270 bottom
C113 "CAP_NP_C0402_DISCRETE_0.1UF" C0402#1 3830,2365 r270 bottom
C114 "CAP_NP_C0402_DISCRETE_10UF" C0402#1 4520,3045 r90 bottom
C115 "CAP_NP_C0402_DISCRETE_0.1UF" C0402#1 4560,3045 r90 bottom
C116 "CAP_NP_C0402_DISCRETE_0.1UF" C0402#1 4345,3080 r270 bottom
C117 "CAP_NP_C0402_DISCRETE_NC" C0402#1 4125,1895 r0 top
C118 "CAP_NP_C0402_DISCRETE_NC" C0402#1 4045,1895 r0 top
C119 "CAP_NP_C0402_DISCRETE_0.1UF" C0402#1 3595.39,3080.24 r270 bottom
C120 "CAP_NP_C0402_DISCRETE_10UF" C0402#1 3770.39,3045.24 r90 bottom
C121 "CAP_NP_C0402_DISCRETE_0.1UF" C0402#1 3810.39,3045.24 r90 bottom
C122 "CAP_NP_C0402_DISCRETE_0.1UF" C0402#1 955,2300 r0 bottom
C123 "CAP_NP_C0402_DISCRETE_10UF" C0402#2 990,2475 r0 bottom
C124 "CAP_NP_C0402_DISCRETE_0.1UF" C0402#2 990,2515 r0 bottom
C125 "CAP_NP_C0402_DISCRETE_0.1UF" C0402#2 4165,1925 r0 bottom
C126 "CAP_NP_C0402_DISCRETE_4.7UF" C0402#2 4165,1845 r0 bottom
C127 "CAP_NP_C0402_DISCRETE_0.1UF" C0402#2 4165,1740 r0 bottom
C128 "CAP_NP_C0402_DISCRETE_0.1UF" C0402#2 4165,1780 r0 bottom
C129 "CAP_NP_C0402_DISCRETE_1UF" C0402#1 2555,2260 r270 bottom
C130 "CAP_NP_C0402_DISCRETE_0.1UF" C0402#1 4760,1205 r90 top
C131 "CAP_NP_C0603_DISCRETE_10UF" C0603#1 4945,1205 r270 top
C132 "CAP_NP_C0402_DISCRETE_0.1UF" C0402#1 4995,1205 r270 top
C133 "CAP_NP_C0402_DISCRETE_0.1UF" C0402#1 4760,2020 r90 top
C134 "CAP_NP_C0603_DISCRETE_10UF" C0603#1 4945,2025 r270 top
C135 "CAP_NP_C0402_DISCRETE_0.1UF" C0402#1 4995,2025 r270 top
C136 "CAP_NP_C0603_DISCRETE_10UF" C0603#1 4945,2200 r270 top
C137 "CAP_NP_C0402_DISCRETE_0.1UF" C0402#1 4995,2200 r270 top
C138 "CAP_NP_C0603_DISCRETE_10UF" C0603#1 4945,1385 r270 top
C139 "CAP_NP_C0402_DISCRETE_0.1UF" C0402#1 4995,1385 r270 top
C140 "CAP_NP_C0402_DISCRETE_0.1UF" C0402#1 4825,2100 r270 bottom
C141 "CAP_NP_C0603_DISCRETE_10UF" C0603#1 4950,2205 r270 bottom
C142 "CAP_NP_C0402_DISCRETE_0.1UF" C0402#1 5000,2205 r270 bottom
C143 "CAP_NP_C0402_DISCRETE_0.1UF" C0402#2 4720,1675 r0 bottom
C144 "CAP_NP_C0603_DISCRETE_10UF" C0603#1 4965,1680 r270 bottom
C145 "CAP_NP_C0402_DISCRETE_0.1UF" C0402#1 5015,1680 r270 bottom
C146 "CAP_NP_C0402_DISCRETE_0.1UF" C0402#1 4850,665 r0 top
C147 "CAP_NP_C0402_DISCRETE_0.1UF" C0402#1 4850,605 r0 top
C148 "CAP_NP_C0402_DISCRETE_0.1UF" C0402#1 4450,1105 r90 bottom
C149 "CAP_NP_C0603_DISCRETE_10UF" C0603#1 4680,1105 r270 bottom
C150 "CAP_NP_C0402_DISCRETE_0.1UF" C0402#1 4975,710 r180 top
C151 "CAP_NP_C0402_DISCRETE_0.1UF" C0402#1 4760,900 r270 top
C152 "CAP_NP_C0603_DISCRETE_10UF" C0603#1 4945,1035 r270 top
C153 "CAP_NP_C0402_DISCRETE_0.1UF" C0402#1 4995,1040 r270 top
C154 "CAP_NP_C0402_DISCRETE_0.1UF" C0402#1 4365,1795 r0 bottom
C155 "CAP_NP_C0402_DISCRETE_NC" C0402#1 4275,1720 r0 bottom
C156 "CAP_NP_C0603_DISCRETE_10UF" C0603#1 4595,1705 r90 bottom
C157 "CAP_NP_C0603_DISCRETE_10UF" C0603#1 4540,1705 r90 bottom
C158 "CAP_NP_C0402_DISCRETE_0.1UF" C0402#1 4490,1705 r90 bottom
C159 "CAP_NP_C0603_DISCRETE_22UF" C0603#1 4395,2070 r0 bottom
C160 "CAP_NP_C0603_DISCRETE_22UF" C0603#1 4395,2130 r0 bottom
C161 "CAP_NP_C0402_DISCRETE_0.1UF" C0402#1 4395,2180 r0 bottom
C162 "CAP_NP_C0402_DISCRETE_33PF" C0402#2 4560,1360 r0 bottom
C163 "CAP_NP_C0402_DISCRETE_33PF" C0402#2 4560,1400 r0 bottom
C164 "CAP_NP_C0402_DISCRETE_33PF" C0402#2 4560,1240 r0 bottom
C165 "CAP_NP_C0402_DISCRETE_0.1UF" C0402#1 4255,1975 r90 top
C166 "CAP_NP_C0402_DISCRETE_0.1UF" C0402#1 4215,1975 r90 top
C167 "CAP_NP_C0402_DISCRETE_0.1UF" C0402#1 3870,2365 r270 bottom
C168 "CAP_NP_C0402_DISCRETE_0.1UF" C0402#1 3640,2170 r270 bottom
C169 "CAP_NP_C0402_DISCRETE_4.7UF" C0402#1 4080,2170 r90 bottom
C170 "CAP_NP_C0402_DISCRETE_4.7UF" C0402#1 4535,2170 r270 bottom
C171 "CAP_NP_C0402_DISCRETE_1UF" C0402#1 1805,2330 r90 top
C172 "CAP_NP_C0402_DISCRETE_0.1UF" C0402#1 1725,2330 r270 top
C173 "CAP_NP_C0402_DISCRETE_1UF" C0402#1 1360,2400 r0 bottom
C174 "CAP_NP_C0603_DISCRETE_100PF" C0603#1 1910,2295 r0 top
C175 "CAP_EC6P3_220UF" EC6P3 1270,2385 r180 top
C176 "CAP_EC6P3_220UF" EC6P3 1550,2385 r180 top
C177 "CAP_NP_C0402_DISCRETE_0.1UF" C0402#1 1765,2475 r90 top
CN1 "WIFI_ANT_UFL-3_WIFI-ANT" UFL-3 4125,395 r180 top
D1 "DIODE BI-DIR TRIG_SMA214-CA_SMA" SMA214-CA 410,2515 r180 top
D2 "DIODE_SOD-123_1N4148W" SOD-123 930,2500 r0 top
D3 "DIODE BI-DIR TRIG_ES0402_KLXES1" ES0402#1 125,2640 r0 top
D4 "DIODE BI-DIR TRIG_ES0402_KLXES1" ES0402#1 125,2285 r0 top
D5 "DIODE BI-DIR TRIG_ES0402_KLXES1" ES0402#1 290,545 r270 bottom
D6 "DIODE BI-DIR TRIG_ES0402_KLXES1" ES0402#1 290,705 r270 bottom
D7 "DIODE BI-DIR TRIG_ES0402_KLXES1" ES0402#1 125,1925 r0 top
D8 "DIODE BI-DIR TRIG_ES0402_KLXES1" ES0402#1 125,1575 r0 top
D9 "BAT54C_SOT23_BAT54C" SOT23#1 699.5,2390 r270 top
D10 "DIODE BI-DIR TRIG_ES0402_KLXES1" ES0402#1 690,2520 r180 top
D11 "DIODE BI-DIR TRIG_SMB-CA_SMBJ15" SMB-CA 1425,920 r270 bottom
D12 "DIODE BI-DIR TRIG_SMB-CA_SMBJ15" SMB-CA 1080,920 r270 bottom
D13 "DIODE BI-DIR TRIG_SMB-CA_SMBJ15" SMB-CA 1260,920 r270 bottom
D14 "DIODE BI-DIR TRIG_SMB-CA_SMBJ15" SMB-CA 915,920 r270 bottom
D15 "DIODE BI-DIR TRIG_ES0402_KLXES1" ES0402#1 4665,630 r0 bottom
D16 "DIODE BI-DIR TRIG_ES0402_KLXES1" ES0402#1 4665,675 r0 bottom
D17 "DIODE BI-DIR TRIG_ES0402_KLXES1" ES0402#1 4665,720 r0 bottom
D18 "DIODE BI-DIR TRIG_ES0402_KLXES1" ES0402#1 4665,830 r0 bottom
D19 "DIODE BI-DIR TRIG_ES0402_KLXES1" ES0402#1 4665,875 r0 bottom
D20 "DIODE BI-DIR TRIG_ES0402_KLXES1" ES0402#1 4665,920 r0 bottom
D21 "DIODE BI-DIR TRIG_ES0402_KLXES1" ES0402#1 4665,965 r0 bottom
D22 "DIODE_SCHTKY_SOD523_IC_RB521S-3" SOD523 2190,1230 r90 bottom
D23 "DIODE_SCHTKY_SOD523_IC_RB521S-3" SOD523 1860,1230 r90 bottom
D24 "DIODE BI-DIR TRIG_SMB-CA_SMBJ6." SMB-CA 1975,920 r270 bottom
D25 "DIODE BI-DIR TRIG_SMB-CA_SMBJ6." SMB-CA 1645,920 r270 bottom
D26 "DIODE BI-DIR TRIG_SMB-CA_SMBJ6." SMB-CA 2140,920 r270 bottom
D27 "DIODE BI-DIR TRIG_SMB-CA_SMBJ6." SMB-CA 1810,920 r270 bottom
D28 "DIODE_SCHTKY_SOD523_IC_RB521S-3" SOD523 2605,2110 r0 bottom
D29 "BAT54A_SOT23_BAT54A" SOT23#1 1209.5,2835 r90 bottom
D30 "DIODE BI-DIR TRIG_ES0402_KLXES1" ES0402#1 1020,2875 r0 bottom
D31 "DIODE BI-DIR TRIG_ES0402_KLXES1" ES0402#2 1100,2875 r0 bottom
D32 "DIODE_SCHTKY_SOD-123_IC_1N5819W" SOD-123 2615,2255 r90 bottom
D33 "DIODE BI-DIR TRIG_ES0402_KLXES1" ES0402#1 2395,2260 r90 bottom
D34 "DIODE BI-DIR TRIG_ES0402_KLXES1" ES0402#1 2680,2380 r90 bottom
D35 "DIODE BI-DIR TRIG_ES0402_KLXES1" ES0402#1 2160,2380 r90 bottom
D36 "DIODE BI-DIR TRIG_ES0402_KLXES1" ES0402#1 2120,2380 r90 bottom
D37 "DIODE BI-DIR TRIG_ES0402_KLXES1" ES0402#1 2515,2260 r90 bottom
D38 "DIODE BI-DIR TRIG_ES0402_KLXES1" ES0402#1 3910,1975 r90 top
D39 "DIODE BI-DIR TRIG_ES0402_KLXES1" ES0402#1 3845,1975 r90 top
D41 "DIODE BI-DIR TRIG_ES0402_KLXES1" ES0402#1 1870,2350 r0 top
D42 "DIODE BI-DIR TRIG_ES0402_KLXES1" ES0402#1 1380,2480 r90 bottom
D43 "DIODE BI-DIR TRIG_ES0402_KLXES1" ES0402#1 1475,2480 r90 bottom
D44 "DIODE BI-DIR TRIG_ES0402_KLXES1" ES0402#1 1950,2350 r180 top
D45 "DIODE BI-DIR TRIG_ES0402_KLXES1" ES0402#1 1180,2480 r90 bottom
D46 "DIODE BI-DIR TRIG_ES0402_KLXES1" ES0402#1 1250,2480 r90 bottom
D47 "DIODE BI-DIR TRIG_ES0402_KLXES1" ES0402#1 3830,400 r270 top
D48 "DIODE BI-DIR TRIG_ES0402_KLXES1" ES0402#1 3790,400 r270 top
D49 "DIODE BI-DIR TRIG_ES0402_KLXES1" ES0402#1 3055,320 r270 bottom
D50 "DIODE BI-DIR TRIG_ES0402_KLXES1" ES0402#1 3015,320 r270 bottom
D51 "DIODE BI-DIR TRIG_ES0402_KLXES1" ES0402#1 3950,400 r270 top
D52 "DIODE BI-DIR TRIG_ES0402_KLXES1" ES0402#1 3910,400 r270 top
D53 "DIODE BI-DIR TRIG_ES0402_KLXES1" ES0402#1 4385,400 r270 top
D54 "DIODE BI-DIR TRIG_ES0402_KLXES1" ES0402#1 4345,400 r270 top
F1 "FUSE_F1812_SMD1812P200TF16" F1812 405,2655 r0 top
H1 "SPACER_NPTH_M3_IC_NPTH_M3" NPTH_M3 157.48,3070.86 r0 top
H2 "SPACER_NPTH_M3_IC_NPTH_M3" NPTH_M3 157.48,157.48 r0 top
H3 "SPACER_NPTH_M3_IC_NPTH_M3" NPTH_M3 5236.21,157.48 r0 top
H4 "SPACER_NPTH_M3_IC_NPTH_M3" NPTH_M3 5236.21,3070.86 r0 top
J1 "DC-044A-20A_DC_IN_TH_3P_10R1X11" DC_IN_TH_3P_10R1X11R6 570.9,3035.03 r270 top
J2 "A1501WV-2P_ZH1P5MM_TH_2P_A1501W" ZH1P5MM_TH_2P 920,2665 r180 top
J3 "1X6PIN_PH-1X6-2P0_PH-6A" PH-1X6-2P0#1 122.36,1208.43 r270 top
J4 "SGDBM-05-80P-H10_SGDBM-05-80P-H" SGDBM-05-80P-H10 1333.85,575.55 r0 top
J5 "SGDBM-05-80P-H10_SGDBF-05-80P-H" SGDBF-05-80P-H30 1333.85,2032.24 r180 top
J6 "SGDBM-05-80P-H10_SGDBM-05-80P-H" SGDBM-05-80P-H10 2318.11,575.55 r0 top
J7 "SGDBM-05-80P-H10_SGDBF-05-80P-H" SGDBF-05-80P-H30 2318.11,2032.24 r180 top
J8 "B2S_DIP-1X2-2P54_1X2PIN-M" DIP-1X2-2P54#1 3270,375 r180 top
J9 "CON4_XH2P54-4P_XH-4A" XH2P54-4P 140,616.54 r90 top
J10 "1.25T-2A_GH1P25_TH_2P_1.25T-2A" GH1P25_TH_2P 689.02,2659.4 r0 top
J11 "CON6_DB2ERC-3P81-6P_CON6" DB2ERC-3P81-6P 866.14,181.85 r180 top
J12 "TF_CARD_TFCARD_IO_TF_CARD" TFCARD 5029.23,650 r270 bottom
J13 "B2S_DIP-1X2-2P54_1X2PIN-M" DIP-1X2-2P54#2 2740,315 r0 top
J14 "B2S_DIP-1X2-2P54_1X2PIN-M" DIP-1X2-2P54#2 2380,315 r0 top
J15 "CON4_DB2ERC-3P81-4P_WJ15EDGRC-3" DB2ERC-3P81-4P 1811.02,181.85 r180 top
J17 "HY911130A_HY911130A_HY911130A" HY911130A 2982.93,2871.61 r0 top
J18 "USB3D0_USB2D0-A-D_USB3D0-AF-18P" USB3D0-AF-18P 3686.28,2963.35 r180 top
J19 "TYPE-C-31-M-12_TYPE-C-31-M-12_T" TYPE-C-31-M-12 1075.93,3092.82 r180 top
J20 "USB-A-D_USB-A-D_USB-A-D" USB-A-D 4435.1,2771.22 r0 top
J21 "FPC-30P_FPC-30P-0P5_FPC_0R5_30P" FPC-30P-0P5 5225.05,2494.99 r90 top
J22 "FPC-30P_FPC-30P-0P5_FPC_0R5_30P" FPC-30P-0P5 5225.05,1624.99 r90 top
J23 "FPC-24P_FPC_24P_0P5_FPC_0P5_24P" FPC_24P_0P5 5241.8,2575 r90 bottom
J24 "FPC-24P_FPC_24P_0P5_FPC_0P5_24P" FPC_24P_0P5 5241.8,1915 r90 bottom
J25 "FPC-30P_FPC-30P-0P5_FPC_0R5_30P" FPC-30P-0P5 5225.05,754.99 r90 top
J26 "1X6PIN_PH-1X6-2P0_PH-6A" PH-1X6-2P0#2 2559.05,128.11 r0 top
J27 "MINI-PCIE_PCIE_52P_MINI-PCIE" PCIE_52P 4102.42,2329.46 r180 top
J28 "MIC_JACK_EAR_JACK_PJ-325C5-G" EAR_JACK 1503.36,2868.97 r270 top
J29 "MIC_JACK_EAR_JACK_PJ-325C5-R" EAR_JACK 1913.58,2868.97 r270 top
J30 "B2S_DIP-1X2-2P54_1X2PIN-M" DIP-1X2-2P54#2 1915,2470 r180 top
J31 "1X2PIN_PH-1X2-2P0_L_PH" PH-1X2-2P0_L 1196.85,2692.91 r0 top
J32 "1X4PIN_PH-1X4-2P0_PH-4A" PH-1X4-2P0 3110.23,128.11 r0 top
J33 "1X4PIN_PH-1X4-2P0_PH-4A" PH-1X4-2P0 3582.67,128.11 r0 top
J34 "1X4PIN_PH-1X4-2P0_PH-4A" PH-1X4-2P0 4055.11,128.11 r0 top
J35 "1X4PIN_PH-1X4-2P0_PH-4A" PH-1X4-2P0 4527.55,128.11 r0 top
L1 "IND_L4520_DISCRETE_3.3UH" L4520 245.1,2224.9 r0 bottom
L2 "IND_L4520_DISCRETE_3.3UH" L4520 245.1,1754.9 r0 bottom
L3 "IND_L4520_DISCRETE_3.3UH" L4520 245.1,2694.9 r0 bottom
L4 "IND_L2520_DISCRETE_2.2UH" L2520 3470,1940 r270 top
L5 "BEAD_L0603_DISCRETE_100R 100MHZ" L0603 3655,1825 r90 top
L6 "BEAD_L0603_DISCRETE_100R 100MHZ" L0603 3045,2260 r90 bottom
L7 "BEAD_L0603_DISCRETE_100R 100MHZ" L0603 3655,1675 r90 top
L8 "BEAD_L0603_DISCRETE_120R 100MHZ" L0603 1080,3135 r0 bottom
L9 "BEAD_L0603_DISCRETE_330R 100MHZ" L0603 2135,2375 r180 top
L10 "IND_L4520_DISCRETE_3.3UH" L4520 4400.1,1935.1 r90 bottom
LED1 "LED_LED0603_RED" LED0603 287,1648.01 r270 top
LED2 "LED_LED0603_BLUE" LED0603 5040,295 r90 top
LED3 "LED_LED0603_BLUE" LED0603 4915,295 r90 top
LED4 "LED_LED0603_BLUE" LED0603 4790,295 r90 top
MARK "ID" MARK#1 866.14,3425.19 r0 bottom
MARK "ID" MARK#2 4448.81,3425.19 r0 bottom
MARK "ID" MARK#3 4724.4,-118.11 r0 bottom
MARK "ID" MARK#4 826.77,-118.11 r0 bottom
MARK "ID" MARK#5 866.14,3425.19 r0 top
MARK "ID" MARK#6 4448.81,3425.19 r0 top
MARK "ID" MARK#7 4724.4,-118.11 r0 top
MARK "ID" MARK#8 826.77,-118.11 r0 top
Q1 "MOSFET_P_SOT23_IC_AO3407" SOT23#1 1060,2390 r270 top
Q2 "NPN_SOT23_IC_SS8050" SOT23#1 870,2390 r270 top
Q3 "NPN_SOT23_IC_SS8050" SOT23#1 445,1334.5 r0 top
Q5 "MOSFET_P_SOT23_IC_AO3407" SOT23#1 400.5,1270 r270 bottom
Q6 "NPN_SOT23_IC_SS8050" SOT23#1 635.5,1405 r270 bottom
Q7 "MOSFET_P_SOT23_IC_AO3407" SOT23#1 3559.5,1170 r270 top
Q8 "2SK3018_SOT23_IC_2SK3018" SOT23#2 2020,2264.5 r0 bottom
Q9 "2SK3018_SOT23_IC_2SK3018" SOT23#2 2190,2264.5 r0 bottom
Q10 "2SK3018_SOT23_IC_2SK3018" SOT23#2 2765,2264.5 r0 bottom
Q12 "MOSFET_P_SOT23_IC_AO3407" SOT23#1 4850,1039.5 r0 top
Q13 "NPN_SOT23_IC_SS8050" SOT23#1 4850,759.5 r0 top
R1 "RES_R0402_DISCRETE_1K" R0402#1 820,1415 r0 bottom
R2 "RES_R0402_DISCRETE_3.4K" R0402#2 735,1270 r90 bottom
R3 "RES_R0402_DISCRETE_1K" R0402#2 620,1650 r90 bottom
R4 "RES_R0402_DISCRETE_100K" R0402#2 110,2055 r0 bottom
R5 "RES_R0402_DISCRETE_6.8K" R0402#2 665,1650 r270 bottom
R6 "RES_R0402_DISCRETE_30K" R0402#1 110,1975 r0 bottom
R7 "RES_R0402_DISCRETE_140K" R0402#2 280,1915 r90 bottom
R8 "RES_R0402_DISCRETE_20K" R0402#2 200,1915 r270 bottom
R9 "RES_R0603_DISCRETE_NC" R0603 955,2240 r0 top
R10 "RES_R0603_DISCRETE_0R" R0603 955,2300 r0 top
R11 "RES_R0402_DISCRETE_115K" R0402#2 110,1605 r0 bottom
R12 "RES_R0402_DISCRETE_20K" R0402#2 965,2390 r90 top
R13 "RES_R0402_DISCRETE_20K" R0402#1 110,1525 r0 bottom
R14 "RES_R0402_DISCRETE_140K" R0402#2 300,1445 r90 bottom
R15 "RES_R0402_DISCRETE_20K" R0402#2 260,1445 r270 bottom
R16 "RES_R0402_DISCRETE_4.7K" R0402#2 287,1770 r270 top
R17 "RES_R0402_DISCRETE_1K" R0402#2 830,2240 r0 top
R18 "RES_R0402_DISCRETE_10K" R0402#2 830,2300 r180 top
R19 "RES_R0402_DISCRETE_1K" R0402#2 445,1205 r180 top
R20 "RES_R0402_DISCRETE_115K" R0402#2 105,2525 r0 bottom
R21 "RES_R0402_DISCRETE_10K" R0402#2 445,1245 r0 top
R22 "RES_R0402_DISCRETE_20K" R0402#1 105,2445 r0 bottom
R23 "RES_R0402_DISCRETE_NC" R0402#2 300,2385 r90 bottom
R24 "RES_R0402_DISCRETE_1K" R0402#2 180,2385 r90 bottom
R25 "RES_R0402_DISCRETE_NC" R0402#2 260,2385 r270 bottom
R26 "RES_R0603_DISCRETE_0R" R0603 525,1270 r270 bottom
R27 "RES_R0402_DISCRETE_20K" R0402#1 500,1420 r0 bottom
R28 "RES_R0402_DISCRETE_510R" R0402#1 640,1250 r0 bottom
R29 "RES_R0402_DISCRETE_10K" R0402#2 640,1295 r0 bottom
R30 "RES_R0402_DISCRETE_1K" R0402#2 540,880 r270 bottom
R31 "RES_R0402_DISCRETE_6.8K" R0402#2 520,950 r0 bottom
R32 "RES_R0402_DISCRETE_1K" R0402#2 540,1060 r270 bottom
R33 "RES_R0402_DISCRETE_6.8K" R0402#2 520,1130 r0 bottom
R34 "RES_R0402_DISCRETE_15K" R0402#2 2070,655 r90 bottom
R35 "RES_R0402_DISCRETE_10K" R0402#2 2150,655 r270 bottom
R36 "RES_R0402_DISCRETE_10K" R0402#2 3445,805 r90 top
R37 "RES_R0402_DISCRETE_10K" R0402#2 3405,805 r90 top
R38 "RES_R0402_DISCRETE_10K" R0402#2 520,545 r270 bottom
R39 "RES_R0402_DISCRETE_510R" R0402#2 330,545 r90 bottom
R40 "RES_R0402_DISCRETE_510R" R0402#2 330,705 r90 bottom
R41 "RES_R0402_DISCRETE_100R" R0402#2 190,1905 r90 top
R42 "RES_R0402_DISCRETE_10K" R0402#2 520,705 r270 bottom
R43 "RES_R0402_DISCRETE_100R" R0402#2 205,1535 r0 top
R44 "RES_R0402_DISCRETE_10K" R0402#2 4995,165 r270 bottom
R45 "RES_R0402_DISCRETE_470R" R0402#2 5040,415 r90 top
R46 "RES_R0402_DISCRETE_22R" R0402#2 4955,165 r270 bottom
R47 "RES_R0402_DISCRETE_22R" R0402#2 4795,165 r90 bottom
R48 "RES_R0402_DISCRETE_470R" R0402#2 4915,415 r90 top
R49 "RES_R0402_DISCRETE_470R" R0402#2 4790,415 r90 top
R50 "RES_R0402_DISCRETE_0R" R0402#2 650,2480 r0 top
R51 "RES_R0402_DISCRETE_NC" R0402#2 730,2480 r0 top
R52 "RES_R0402_DISCRETE_10K" R0402#1 1455,1180 r0 bottom
R53 "RES_R0402_DISCRETE_10K" R0402#1 1455,1220 r0 bottom
R54 "RES_R0402_DISCRETE_10K" R0402#1 1455,1300 r0 bottom
R55 "RES_R0402_DISCRETE_10K" R0402#1 1455,1260 r0 bottom
R56 "RES_R0603_DISCRETE_0R" R0603 1420,705 r270 bottom
R57 "RES_R0603_DISCRETE_0R" R0603 1260,705 r270 bottom
R58 "RES_R0603_DISCRETE_0R" R0603 1100,705 r270 bottom
R59 "RES_R0603_DISCRETE_0R" R0603 900,700 r270 bottom
R60 "RES_R0402_DISCRETE_22R" R0402#2 4560,630 r0 bottom
R61 "RES_R0402_DISCRETE_22R" R0402#2 4560,675 r0 bottom
R62 "RES_R0402_DISCRETE_22R" R0402#2 4560,720 r0 bottom
R63 "RES_R0402_DISCRETE_22R" R0402#2 4560,830 r0 bottom
R64 "RES_R0402_DISCRETE_22R" R0402#2 4560,875 r0 bottom
R65 "RES_R0402_DISCRETE_22R" R0402#2 4560,920 r0 bottom
R66 "RES_R0402_DISCRETE_0R" R0402#2 4560,965 r0 bottom
R67 "RES_R0402_DISCRETE_10K" R0402#2 2190,1320 r90 bottom
R68 "RES_R0402_DISCRETE_10K" R0402#2 1860,1320 r90 bottom
R69 "RES_R0402_DISCRETE_10K" R0402#2 1920,1320 r90 bottom
R70 "RES_R0402_DISCRETE_10K" R0402#2 1590,1320 r90 bottom
R71 "RES_R0402_DISCRETE_4.7K" R0402#1 2100,1105 r0 bottom
R72 "RES_R0402_DISCRETE_4.7K" R0402#1 1770,1105 r0 bottom
R73 "RES_R0603_DISCRETE_120R" R0603 2590,315 r90 top
R74 "RES_R0603_DISCRETE_120R" R0603 2525,315 r90 top
R75 "RES_R0402_DISCRETE_10K" R0402#2 2055,1460 r0 bottom
R76 "RES_R0402_DISCRETE_4.7K" R0402#1 2010,1105 r0 bottom
R77 "RES_R0402_DISCRETE_10K" R0402#2 1730,1460 r0 bottom
R78 "RES_R0402_DISCRETE_4.7K" R0402#1 1680,1105 r0 bottom
R79 "RES_R0603_DISCRETE_0R" R0603 1990,150 r90 bottom
R80 "RES_R0603_DISCRETE_0R" R0603 1930,150 r90 bottom
R81 "RES_R0603_DISCRETE_0R" R0603 1690,150 r90 bottom
R82 "RES_R0603_DISCRETE_0R" R0603 1630,150 r90 bottom
R89 "RES_R0402_DISCRETE_NC" R0402#2 3450,1840 r270 bottom
R90 "RES_R0402_DISCRETE_NC" R0402#2 3470,1675 r270 top
R91 "RES_R0402_DISCRETE_0R" R0402#2 3430,1675 r90 top
R92 "RES_R0402_DISCRETE_0R" R0402#2 3490,1840 r270 bottom
R93 "RES_R0402_DISCRETE_4.7K" R0402#2 3310,1675 r90 top
R94 "RES_R0402_DISCRETE_4.7K" R0402#2 3270,1675 r90 top
R95 "RES_R0402_DISCRETE_4.7K" R0402#2 3390,1675 r90 top
R96 "RES_R0402_DISCRETE_22R" R0402#2 3310,1775 r90 top
R97 "RES_R0402_DISCRETE_22R" R0402#2 3270,1775 r90 top
R98 "RES_R0402_DISCRETE_2.49K" R0402#2 3260,2290 r90 top
R99 "RES_R0402_DISCRETE_22R" R0402#2 3230,1775 r90 top
R100 "RES_R0402_DISCRETE_22R" R0402#2 3190,1775 r90 top
R101 "RES_R0402_DISCRETE_22R" R0402#2 3390,1775 r90 top
R102 "RES_R0402_DISCRETE_22R" R0402#2 3350,1775 r90 top
R103 "RES_R0402_DISCRETE_4.7K" R0402#2 3230,1675 r270 top
R104 "RES_R0402_DISCRETE_4.7K" R0402#2 3190,1675 r270 top
R105 "RES_R0402_DISCRETE_4.7K" R0402#2 3350,1675 r270 top
R106 "RES_R0402_DISCRETE_NC" R0402#2 3110,1675 r90 top
R107 "RES_R0402_DISCRETE_0R" R0402#2 3150,1675 r270 top
R108 "RES_R0402_DISCRETE_4.7K" R0402#2 3110,1775 r90 top
R109 "RES_R0402_DISCRETE_4.7K" R0402#2 3150,1775 r90 top
R110 "RES_R0402_DISCRETE_4.7K" R0402#2 3605,1945 r90 top
R111 "RES_R0402_DISCRETE_NC" R0402#2 3565,1945 r90 top
R112 "RES_R0402_DISCRETE_0R" R0402#2 3705,1945 r90 top
R113 "RES_R0402_DISCRETE_NC" R0402#2 3745,1945 r90 top
R114 "RES_R0402_DISCRETE_510R" R0402#2 2960,3050 r90 bottom
R115 "RES_R0402_DISCRETE_510R" R0402#2 3000,3050 r90 bottom
R116 "RES_R0402_DISCRETE_4.7K" R0402#2 3430,2035 r270 bottom
R117 "RES_R0402_DISCRETE_4.7K" R0402#2 3550,2035 r270 bottom
R118 "RES_R0402_DISCRETE_4.7K" R0402#2 3655,1945 r270 top
R119 "RES_R0402_DISCRETE_NC" R0402#2 2730,2145 r90 bottom
R120 "RES_R0402_DISCRETE_10K" R0402#2 2690,2145 r90 bottom
R121 "RES_R0402_DISCRETE_0R" R0402#2 3510,2035 r270 bottom
R122 "RES_R0402_DISCRETE_NC" R0402#2 3470,2035 r270 bottom
R123 "RES_R0402_DISCRETE_0R" R0402#2 3380,1840 r270 bottom
R124 "RES_R0402_DISCRETE_0R" R0402#2 3240,1840 r90 bottom
R125 "RES_R0402_DISCRETE_2.2R" R0402#2 3700,925 r0 top
R126 "RES_R0402_DISCRETE_2.2R" R0402#2 3700,965 r0 top
R127 "RES_R0402_DISCRETE_10K" R0402#2 3465,1170 r90 top
R128 "RES_R0402_DISCRETE_510R" R0402#2 3365,1170 r90 top
R129 "RES_R0402_DISCRETE_2.2R" R0402#2 3495,2365 r270 bottom
R130 "RES_R0402_DISCRETE_2.2R" R0402#2 3535,2365 r270 bottom
R131 "RES_R0402_DISCRETE_2.2R" R0402#2 4300,2365 r270 bottom
R132 "RES_R0402_DISCRETE_2.2R" R0402#2 4260,2365 r270 bottom
R133 "RES_R0402_DISCRETE_2.2R" R0402#2 1040,2815 r270 bottom
R134 "RES_R0402_DISCRETE_2.2R" R0402#2 1080,2815 r270 bottom
R135 "RES_R0402_DISCRETE_100R" R0402#2 1300,2835 r270 bottom
R136 "RES_R0402_DISCRETE_2.2R" R0402#2 3750,2365 r270 bottom
R137 "RES_R0402_DISCRETE_2.2R" R0402#2 3710,2365 r270 bottom
R138 "RES_R0402_DISCRETE_2.2R" R0402#2 4220,2365 r270 bottom
R139 "RES_R0402_DISCRETE_2.2R" R0402#2 4180,2365 r270 bottom
R140 "RES_R0402_DISCRETE_1K" R0402#2 4305,3080 r90 bottom
R141 "RES_R0402_DISCRETE_2.2R" R0402#2 3910,1565 r180 top
R142 "RES_R0402_DISCRETE_2.2R" R0402#2 3910,1605 r180 top
R143 "RES_R0402_DISCRETE_3.4K" R0402#2 4345,3000 r90 bottom
R144 "RES_R0402_DISCRETE_100K" R0402#2 4095,1650 r270 bottom
R145 "RES_R0402_DISCRETE_100K" R0402#2 4135,1650 r270 bottom
R146 "RES_R0402_DISCRETE_1K" R0402#2 3555.39,3080.24 r90 bottom
R147 "RES_R0402_DISCRETE_3.4K" R0402#2 3595.39,3000.24 r90 bottom
R148 "RES_R0402_DISCRETE_10K" R0402#2 945,2815 r90 bottom
R149 "RES_R0402_DISCRETE_1K" R0402#1 955,2260 r0 bottom
R150 "RES_R0402_DISCRETE_15K" R0402#2 905,2815 r270 bottom
R151 "RES_R0603_DISCRETE_0R" R0603 4245,1885 r270 bottom
R152 "RES_R0402_DISCRETE_6.8K" R0402#1 1040,2300 r0 bottom
R153 "RES_R0402_DISCRETE_1K" R0402#2 2475,2260 r90 bottom
R154 "RES_R0402_DISCRETE_100K" R0402#2 2435,2260 r270 bottom
R155 "RES_R0402_DISCRETE_27K" R0402#2 1935,2260 r270 bottom
R156 "RES_R0402_DISCRETE_10K" R0402#2 2105,2260 r270 bottom
R157 "RES_R0402_DISCRETE_2.2K" R0402#2 2275,2260 r270 bottom
R158 "RES_R0402_DISCRETE_10K" R0402#2 2680,2260 r270 bottom
R159 "RES_R0402_DISCRETE_2.2K" R0402#2 2850,2260 r90 bottom
R160 "RES_R0402_DISCRETE_0R" R0402#2 4870,2450 r0 top
R161 "RES_R0402_DISCRETE_0R" R0402#2 4970,1640 r0 top
R162 "RES_R0402_DISCRETE_10K" R0402#2 4970,2375 r0 bottom
R163 "RES_R0402_DISCRETE_10K" R0402#2 4970,2495 r0 bottom
R164 "RES_R0402_DISCRETE_10K" R0402#2 4970,1560 r0 top
R165 "RES_R0402_DISCRETE_10K" R0402#2 4970,1480 r0 top
R166 "RES_R0402_DISCRETE_10K" R0402#2 4970,2415 r0 bottom
R167 "RES_R0402_DISCRETE_10K" R0402#2 4970,2455 r0 bottom
R168 "RES_R0402_DISCRETE_10K" R0402#2 4970,1600 r0 top
R169 "RES_R0402_DISCRETE_10K" R0402#2 4970,1520 r0 top
R170 "RES_R0402_DISCRETE_1K" R0402#2 4760,1120 r90 top
R171 "RES_R0402_DISCRETE_1K" R0402#2 4760,1935 r90 top
R172 "RES_R0402_DISCRETE_6.8K" R0402#2 4760,1290 r90 top
R173 "RES_R0402_DISCRETE_6.8K" R0402#2 4760,2105 r90 top
R174 "RES_R0402_DISCRETE_6.8K" R0402#2 4760,2200 r270 top
R175 "RES_R0402_DISCRETE_6.8K" R0402#2 4760,1385 r270 top
R176 "RES_R0402_DISCRETE_0R" R0402#2 4940,2655 r0 bottom
R177 "RES_R0402_DISCRETE_NC" R0402#1 4900.55,2655 r0 bottom
R178 "RES_R0402_DISCRETE_0R" R0402#2 4940,2695 r0 bottom
R179 "RES_R0402_DISCRETE_1K" R0402#2 4785,2100 r90 bottom
R180 "RES_R0402_DISCRETE_NC" R0402#1 4900.65,2695 r0 bottom
R181 "RES_R0402_DISCRETE_6.8K" R0402#2 4865,2100 r270 bottom
R182 "RES_R0402_DISCRETE_0R" R0402#2 4940,2735 r0 bottom
R183 "RES_R0402_DISCRETE_NC" R0402#1 4900.65,2735 r0 bottom
R184 "RES_R0402_DISCRETE_0R" R0402#2 4940,2775 r0 bottom
R185 "RES_R0402_DISCRETE_NC" R0402#1 4900.65,2775 r0 bottom
R186 "RES_R0402_DISCRETE_1K" R0402#2 4720,1715 r0 bottom
R187 "RES_R0402_DISCRETE_6.8K" R0402#1 4720,1635 r0 bottom
R188 "RES_R0402_DISCRETE_NC" R0402#2 4975,605 r0 top
R189 "RES_R0402_DISCRETE_10K" R0402#2 2415,485 r0 bottom
R190 "RES_R0402_DISCRETE_10K" R0402#2 2415,525 r0 bottom
R191 "RES_R0402_DISCRETE_NC" R0402#2 4975,665 r0 top
R192 "RES_R0402_DISCRETE_1K" R0402#2 4410,1105 r270 bottom
R193 "RES_R0603_DISCRETE_0R" R0603 4855,900 r0 top
R194 "RES_R0402_DISCRETE_6.8K" R0402#1 4560,1020 r0 bottom
R195 "RES_R0402_DISCRETE_20K" R0402#2 4720,900 r270 top
R196 "RES_R0402_DISCRETE_1K" R0402#2 4720,755 r270 top
R197 "RES_R0402_DISCRETE_10K" R0402#2 4760,755 r90 top
R198 "RES_R0402_DISCRETE_15K" R0402#2 4560,1280 r0 bottom
R199 "RES_R0402_DISCRETE_0R" R0402#2 4560,1200 r0 bottom
R200 "RES_R0402_DISCRETE_0R" R0402#2 4560,1440 r0 bottom
R201 "RES_R0402_DISCRETE_100K" R0402#2 4275,1760 r0 bottom
R202 "RES_R0402_DISCRETE_0R" R0402#2 4560,1320 r0 bottom
R203 "RES_R0402_DISCRETE_30K" R0402#1 4275,1680 r0 bottom
R204 "RES_R0402_DISCRETE_0R" R0402#2 4275,1640 r0 bottom
R205 "RES_R0402_DISCRETE_4.7K" R0402#2 4390,2365 r90 bottom
R206 "RES_R0402_DISCRETE_22R" R0402#2 4430,2365 r90 bottom
R207 "RES_R0402_DISCRETE_22R" R0402#2 4470,2365 r90 bottom
R208 "RES_R0402_DISCRETE_100R" R0402#2 4160,2170 r270 bottom
R209 "RES_R0402_DISCRETE_100R" R0402#2 4120,2170 r270 bottom
R210 "RES_R0402_DISCRETE_2.2R" R0402#2 3910,1885 r0 top
R211 "RES_R0402_DISCRETE_2.2R" R0402#2 3910,1845 r0 top
R212 "RES_R0402_DISCRETE_120R" R0402#2 1765,2330 r270 top
R213 "RES_R0402_DISCRETE_2.2K" R0402#2 1870,2245 r0 top
R214 "RES_R0402_DISCRETE_10K" R0402#2 1725,2475 r90 top
R215 "RES_R0402_DISCRETE_22R" R0402#2 1340,2480 r90 bottom
R216 "RES_R0402_DISCRETE_0R" R0402#2 1435,2480 r270 bottom
R217 "RES_R0402_DISCRETE_2.2K" R0402#2 1950,2245 r0 top
R218 "RES_R0402_DISCRETE_0R" R0402#2 2160,3015 r270 bottom
R219 "RES_R0402_DISCRETE_510R" R0402#2 3790,505 r90 top
R220 "RES_R0402_DISCRETE_510R" R0402#2 3830,505 r90 top
R221 "RES_R0402_DISCRETE_510R" R0402#2 3095,320 r90 bottom
R222 "RES_R0402_DISCRETE_510R" R0402#2 2975,320 r90 bottom
R223 "RES_R0402_DISCRETE_510R" R0402#2 3950,505 r90 top
R224 "RES_R0402_DISCRETE_510R" R0402#2 3910,505 r90 top
R225 "RES_R0402_DISCRETE_510R" R0402#2 4385,505 r90 top
R226 "RES_R0402_DISCRETE_510R" R0402#2 4345,505 r90 top
R227 "RES_R0402_DISCRETE_10K" R0402#2 205,1575 r0 top
SS1 "SPACER_SMTSO-M2R5_IC_M2.5X4MM" SMTSO-M2R5 723.62,575.55 r0 top
SS2 "SPACER_SMTSO-M2R5_IC_M2.5X4MM" SMTSO-M2R5 2928.34,575.55 r0 top
SS3 "SPACER_SMTSO-M2R5_IC_M2.5X4MM" SMTSO-M2R5 723.62,2032.24 r0 top
SS4 "SPACER_SMTSO-M2R5_IC_M2.5X4MM" SMTSO-M2R5 2928.34,2032.24 r0 top
SS5 "SPACER_T3R2-5R2_TOPSMT_IC_M2X3M" T3R2-5R2_TOPSMT 3626.03,437.78 r0 top
SS6 "SPACER_T3R2-5R2_TOPSMT_IC_M2X3M" T3R2-5R2_TOPSMT 4578.79,437.78 r0 top
SW1 "SW_PB_ESW_SW_3_2X4_2_IC_SW_PB_E" SW_3_2X4_2 125,2774.96 r90 top
SW2 "SW_PB_ESW_SW_3_2X4_2_IC_SW_PB_E" SW_3_2X4_2 125,2420.02 r90 top
SW3 "SW_PB_ESW_SW_3_2X4_2_IC_SW_PB_E" SW_3_2X4_2 125,2065 r90 top
SW4 "SW_PB_ESW_SW_3_2X4_2_IC_SW_PB_E" SW_3_2X4_2 124.38,1710.56 r90 top
U1 "MT9700_SOT23-5_MT9700" SOT23-5#1 820,1270 r0 bottom
U2 "MT9700_SOT23-5_MT9700" SOT23-5#2 625,1755 r270 bottom
U3 "TP6327GS6_SOT23_6_TP6327GS6" SOT23_6 240,2015 r270 bottom
U4 "TP6327GS6_SOT23_6_TP6327GS6" SOT23_6 240,1545 r270 bottom
U5 "TP6327GS6_SOT23_6_TP6327GS6" SOT23_6 240,2485 r270 bottom
U6 "MT9700_SOT23-5_MT9700" SOT23-5#2 405,905 r0 bottom
U7 "MT9700_SOT23-5_MT9700" SOT23-5#2 405,1085 r0 bottom
U8 "W25QXX_8P_SOIC8-208_NC" SOIC8-208 3270,760 r270 top
U9 "74LVC1G125_SOT-353_74LVC1G125GW" SOT-353 404.69,545 r0 bottom
U10 "74LVC1G125_SOT-353_74LVC1G125GW" SOT-353 404.69,705 r0 bottom
U11 "IRM-V838M3-C/TR1_SMD4-6R80X2R50" SMD4-6R80X2R50 4915,101.18 r180 top
U12 "RX8010SJ_SOP-8_RX8010SJ" SOP-8 709.85,2400.07 r270 bottom
U13 "MAX3232CSE_SOIC16_MAX3232CSE" SOIC16 1170,1270 r270 bottom
U14 "TJA1057GT3_SOP8_IC_MAX3485" SOP8 2055.32,1270.75 r0 bottom
U15 "TJA1057GT3_SOP8_IC_MAX3485" SOP8 1725.32,1270.75 r0 bottom
U16 "RTL8211F_QFP_40P_R_JL2101-N040C" QFP_40P_R 3265,2040 r315 top
U17 "RTL8723_RL-UM02WBS-8723BU_TL882" RL-UM02WBS-8723BU 4102.42,923.61 r180 top
U18 "RCLAMP0524P_USON_10_RCLAMP0524P" USON_10#1 3635,2480 r0 bottom
U19 "RCLAMP0524P_USON_10_RCLAMP0524P" USON_10#1 3770,2480 r0 bottom
U20 "RCLAMP0524P_USON_10_RCLAMP0524P" USON_10#1 4240,2480 r0 bottom
U21 "MT9700_SOT23-5_MT9700" SOT23-5#1 4435,3045 r0 bottom
U22 "CH334F_QFN24_CH334F" QFN24 4085,1735 r270 top
U23 "MT9700_SOT23-5_MT9700" SOT23-5#1 3685.39,3045.24 r0 bottom
U24 "MT9700_SOT23-5_MT9700" SOT23-5#2 990,2390 r270 bottom
U25 "HDMI-001C_HDMI-SMD_IO_HDMI-001C" HDMI-SMD 2414.86,2844.83 r90 top
U26 "RCLAMP0524P_USON_10_RCLAMP0524P" USON_10#2 2160,2710 r90 bottom
U27 "RCLAMP0524P_USON_10_RCLAMP0524P" USON_10#2 2160,2570 r90 bottom
U28 "MT9700_SOT23-5_MT9700" SOT23-5#2 4850,2020 r180 top
U29 "MT9700_SOT23-5_MT9700" SOT23-5#2 4850,1205 r180 top
U30 "MT9700_SOT23-5_MT9700" SOT23-5#2 4850,2200 r180 top
U31 "MT9700_SOT23-5_MT9700" SOT23-5#2 4850,1385 r180 top
U32 "MT9700_SOT23-5_MT9700" SOT23-5#2 4830,2205 r270 bottom
U33 "MT9700_SOT23-5_MT9700" SOT23-5#2 4855,1675 r270 bottom
U34 "MT9700_SOT23-5_MT9700" SOT23-5#2 4560,1105 r270 bottom
U35 "TP6327GS6_SOT23_6_TP6327GS6" SOT23_6 4395,1705 r270 bottom
U36 "SIM-7-1_NANO_SIM_SIM-7-1" NANO_SIM 5094.47,1280 r270 bottom
U37 "NUP5120-D_SOT563_NUP5120X6T1G" SOT563 4670.04,1319.02 r0 bottom
Y1 "CRYSTAL_4P_3225_IC_25MHZ" 3225 3380,2370 r0 top
Y2 "CRYSTAL_4P_3225_IC_12MHZ" 3225 4085,1975 r180 top

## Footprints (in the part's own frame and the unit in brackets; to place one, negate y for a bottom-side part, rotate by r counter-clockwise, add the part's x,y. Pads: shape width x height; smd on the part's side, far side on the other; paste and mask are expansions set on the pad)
3225 [mm] "3225"
  rect 1.3x1 smd: 1(-1.15,-0.75) 2(1.15,-0.75) 3(1.15,0.75) 4(-1.15,0.75)
  silkscreen extent -1.52,-1.91 0.3,1.2, body extent -1.9,-1.4 1.9,1.4, height 3.81
C0402#1 [mil] "C0402"
  rect 23.6x23.6 smd: 1(-19.68,0) 2(19.68,0)
  silkscreen extent -37,-17 37,17, body extent -37,-17 37,17, height 150
C0402#2 [mil] "C0402"
  rect 23.6x23.6 smd: 1(19.68,0) 2(-19.68,0)
  silkscreen extent -37,-17 37,17, body extent -37,-17 37,17, height 150
C0603#1 [mil] "C0603"
  rect 31.5x31.5 smd: 1(-31.5,0) 2(31.5,0)
  silkscreen extent -55,-25 55,25, body extent -48,-16 48,16, height 150
C0603#2 [mil] "C0603"
  rect 31.5x31.5 smd: 1(31.5,0) 2(-31.5,0)
  silkscreen extent -55,-25 55,25, body extent -48,-16 48,16, height 150
DB2ERC-3P81-4P [mm] "DB2ERC-3P81-4P"
  rect 1.8x1.8 / inner round 1.524 / far side rect 1.8x1.8 hole 1.2: 1(-5.725,-3.5)
  round 1.8 / inner round 1.524 / far side round 1.8 hole 1.2: 2(-1.915,-3.5) 3(1.895,-3.5) 4(5.705,-3.5)
  silkscreen extent -8.13,-5.35 8.11,4.55, body extent -8.2,-4.7 8.2,4.7, height 3.81
DB2ERC-3P81-6P [mm] "DB2ERC-3P81-6P"
  rect 1.8x1.8 / inner round 1.524 / far side rect 1.8x1.8 hole 1.2: 1(-9.525,-3.5)
  round 1.8 hole 1.2: 2(-5.715,-3.5) 5(5.715,-3.5)
  round 1.8 / inner round 1.524 / far side round 1.8 hole 1.2: 3(-1.905,-3.5) 4(1.905,-3.5) 6(9.525,-3.5)
  silkscreen extent -11.93,-5.35 11.93,4.55, body extent -12,-4.7 12,4.7, height 3.81
DC_IN_TH_3P_10R1X11R6 [mil] "DC_IN_TH_3P_10R1X11R6"
  oval 94.5x39.4 hole 70.9 slot 15.7 at 90 deg: 1(-111.25,-194.9) 5(-111.25,190.9)
  oval 102.4x43.3 hole 66.9 slot 19.7 at 90 deg: 2(174.25,-51.2) 3(174.25,157.4)
  oval 102.4x43.3 / inner round 60 / far side oval 102.4x43.3 hole 66.9 slot 19.7 at 90 deg: 4(174.25,-177.2)
  round 78.7 hole 78.7 unplated: ""(-69.85,-51.2)
  silkscreen extent -232,-201 226,197, body extent -237,-228 237,228, height 150
DIP-1X2-2P54#1 [mil] "DIP-1X2-2P54"
  rect 59.06x59.06 hole 35.43: 1(-50,0)
  round 59.06 / inner round 60 / far side round 59.06 hole 35.43: 2(50,0)
  silkscreen extent -100,-50 100,50, body extent -100,-50 100,50, height 150
DIP-1X2-2P54#2 [mil] "DIP-1X2-2P54"
  rect 59.06x59.06 / inner round 60 / far side rect 59.06x59.06 hole 35.43: 1(-50,0)
  round 59.06 / inner round 60 / far side round 59.06 hole 35.43: 2(50,0)
  silkscreen extent -100,-50 100,50
EAR_JACK [mm] "EAR_JACK"
  oval 1.4x2.6 / inner round 1.524 / far side oval 1.4x2.6 hole 1 slot 2 at 90 deg: 1(-5.904,-0.05) 2(-3.504,1.95) 3(1.996,1.95) 4(6.096,-0.05) 5(0.196,-0.05)
  silkscreen extent -11.12,-4.06 7.2,4.06, body extent -7.2,-4.15 7.2,4.15, height 3.81
EC6P3 [mil] "EC6P3"
  rect 39.4x78.7 smd: 1(0,110.24) 2(0,-110.24)
  silkscreen extent -130,-130 130,130, body extent -138,-157 138,157, height 150
ES0402#1 [mil] "ES0402"
  rect 23.6x23.6 smd: 1(-19.68,0) 2(19.68,0)
  silkscreen extent -37,-17 37,17, body extent -37,-17 37,17, height 150
ES0402#2 [mil] "ES0402"
  rect 23.6x23.6 smd: 1(19.68,0) 2(-19.68,0)
  silkscreen extent -37,-17 37,17, body extent -37,-17 37,17, height 150
F1812 [mm] "F1812"
  rect 1.78x3.3 smd: 1(-2.305,0) 2(2.305,0)
  silkscreen extent -3.4,-1.9 3.4,1.9
FPC-30P-0P5 [mm] "FPC-30P-0P5"
  rect 0.3x1.3 smd: 1(-7.25,2.733) 2(-6.75,2.733) 3(-6.25,2.733) 4(-5.75,2.733) 5(-5.25,2.733) 6(-4.75,2.733) 7(-4.25,2.733) 8(-3.75,2.733) 9(-3.25,2.733) 10(-2.75,2.733) 11(-2.25,2.733) 12(-1.75,2.733) 13(-1.25,2.733) 14(-0.75,2.733) 15(-0.25,2.733) 16(0.25,2.733) 17(0.75,2.733) 18(1.25,2.733) 19(1.75,2.733) 20(2.25,2.733) 21(2.75,2.733) 22(3.25,2.733) 23(3.75,2.733) 24(4.25,2.733) 25(4.75,2.733) 26(5.25,2.733) 27(5.75,2.733) 28(6.25,2.733) 29(6.75,2.733) 30(7.25,2.733)
  rect 1.6x2 smd: 31(9.4,0.032) 32(-9.4,0.032)
  silkscreen extent -10.05,-3.27 10.05,4.14, body extent -10.05,-3.35 10.05,3.35, height 3.81
FPC_24P_0P5 [mm] "FPC_24P_0P5"
  rect 0.3x1.3 smd: 1(-5.75,-2.701) 2(-5.25,-2.701) 3(-4.75,-2.701) 4(-4.25,-2.701) 5(-3.75,-2.701) 6(-3.25,-2.701) 7(-2.75,-2.701) 8(-2.25,-2.701) 9(-1.75,-2.701) 10(-1.25,-2.701) 11(-0.75,-2.701) 12(-0.25,-2.701) 13(0.25,-2.701) 14(0.75,-2.701) 15(1.25,-2.701) 16(1.75,-2.701) 17(2.25,-2.701) 18(2.75,-2.701) 19(3.25,-2.701) 20(3.75,-2.701) 21(4.25,-2.701) 22(4.75,-2.701) 23(5.25,-2.701) 24(5.75,-2.701)
  rect 1.6x2 smd: 25(7.45,0.001) 26(-7.45,0.001)
  silkscreen extent -8.1,-3.95 8.1,3.35
GH1P25_TH_2P [mm] "GH1P25_TH_2P"
  rect 0.9x0.9 / inner round 1.524 / far side rect 0.9x0.9 hole 0.5: 1(-0.626,-0.849)
  round 0.9 hole 0.5: 2(0.624,-0.849)
  silkscreen extent -2.2,-1.75 2.2,1.75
